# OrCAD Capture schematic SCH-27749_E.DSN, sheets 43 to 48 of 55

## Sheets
43 88E1543 1G Phy #2: size C
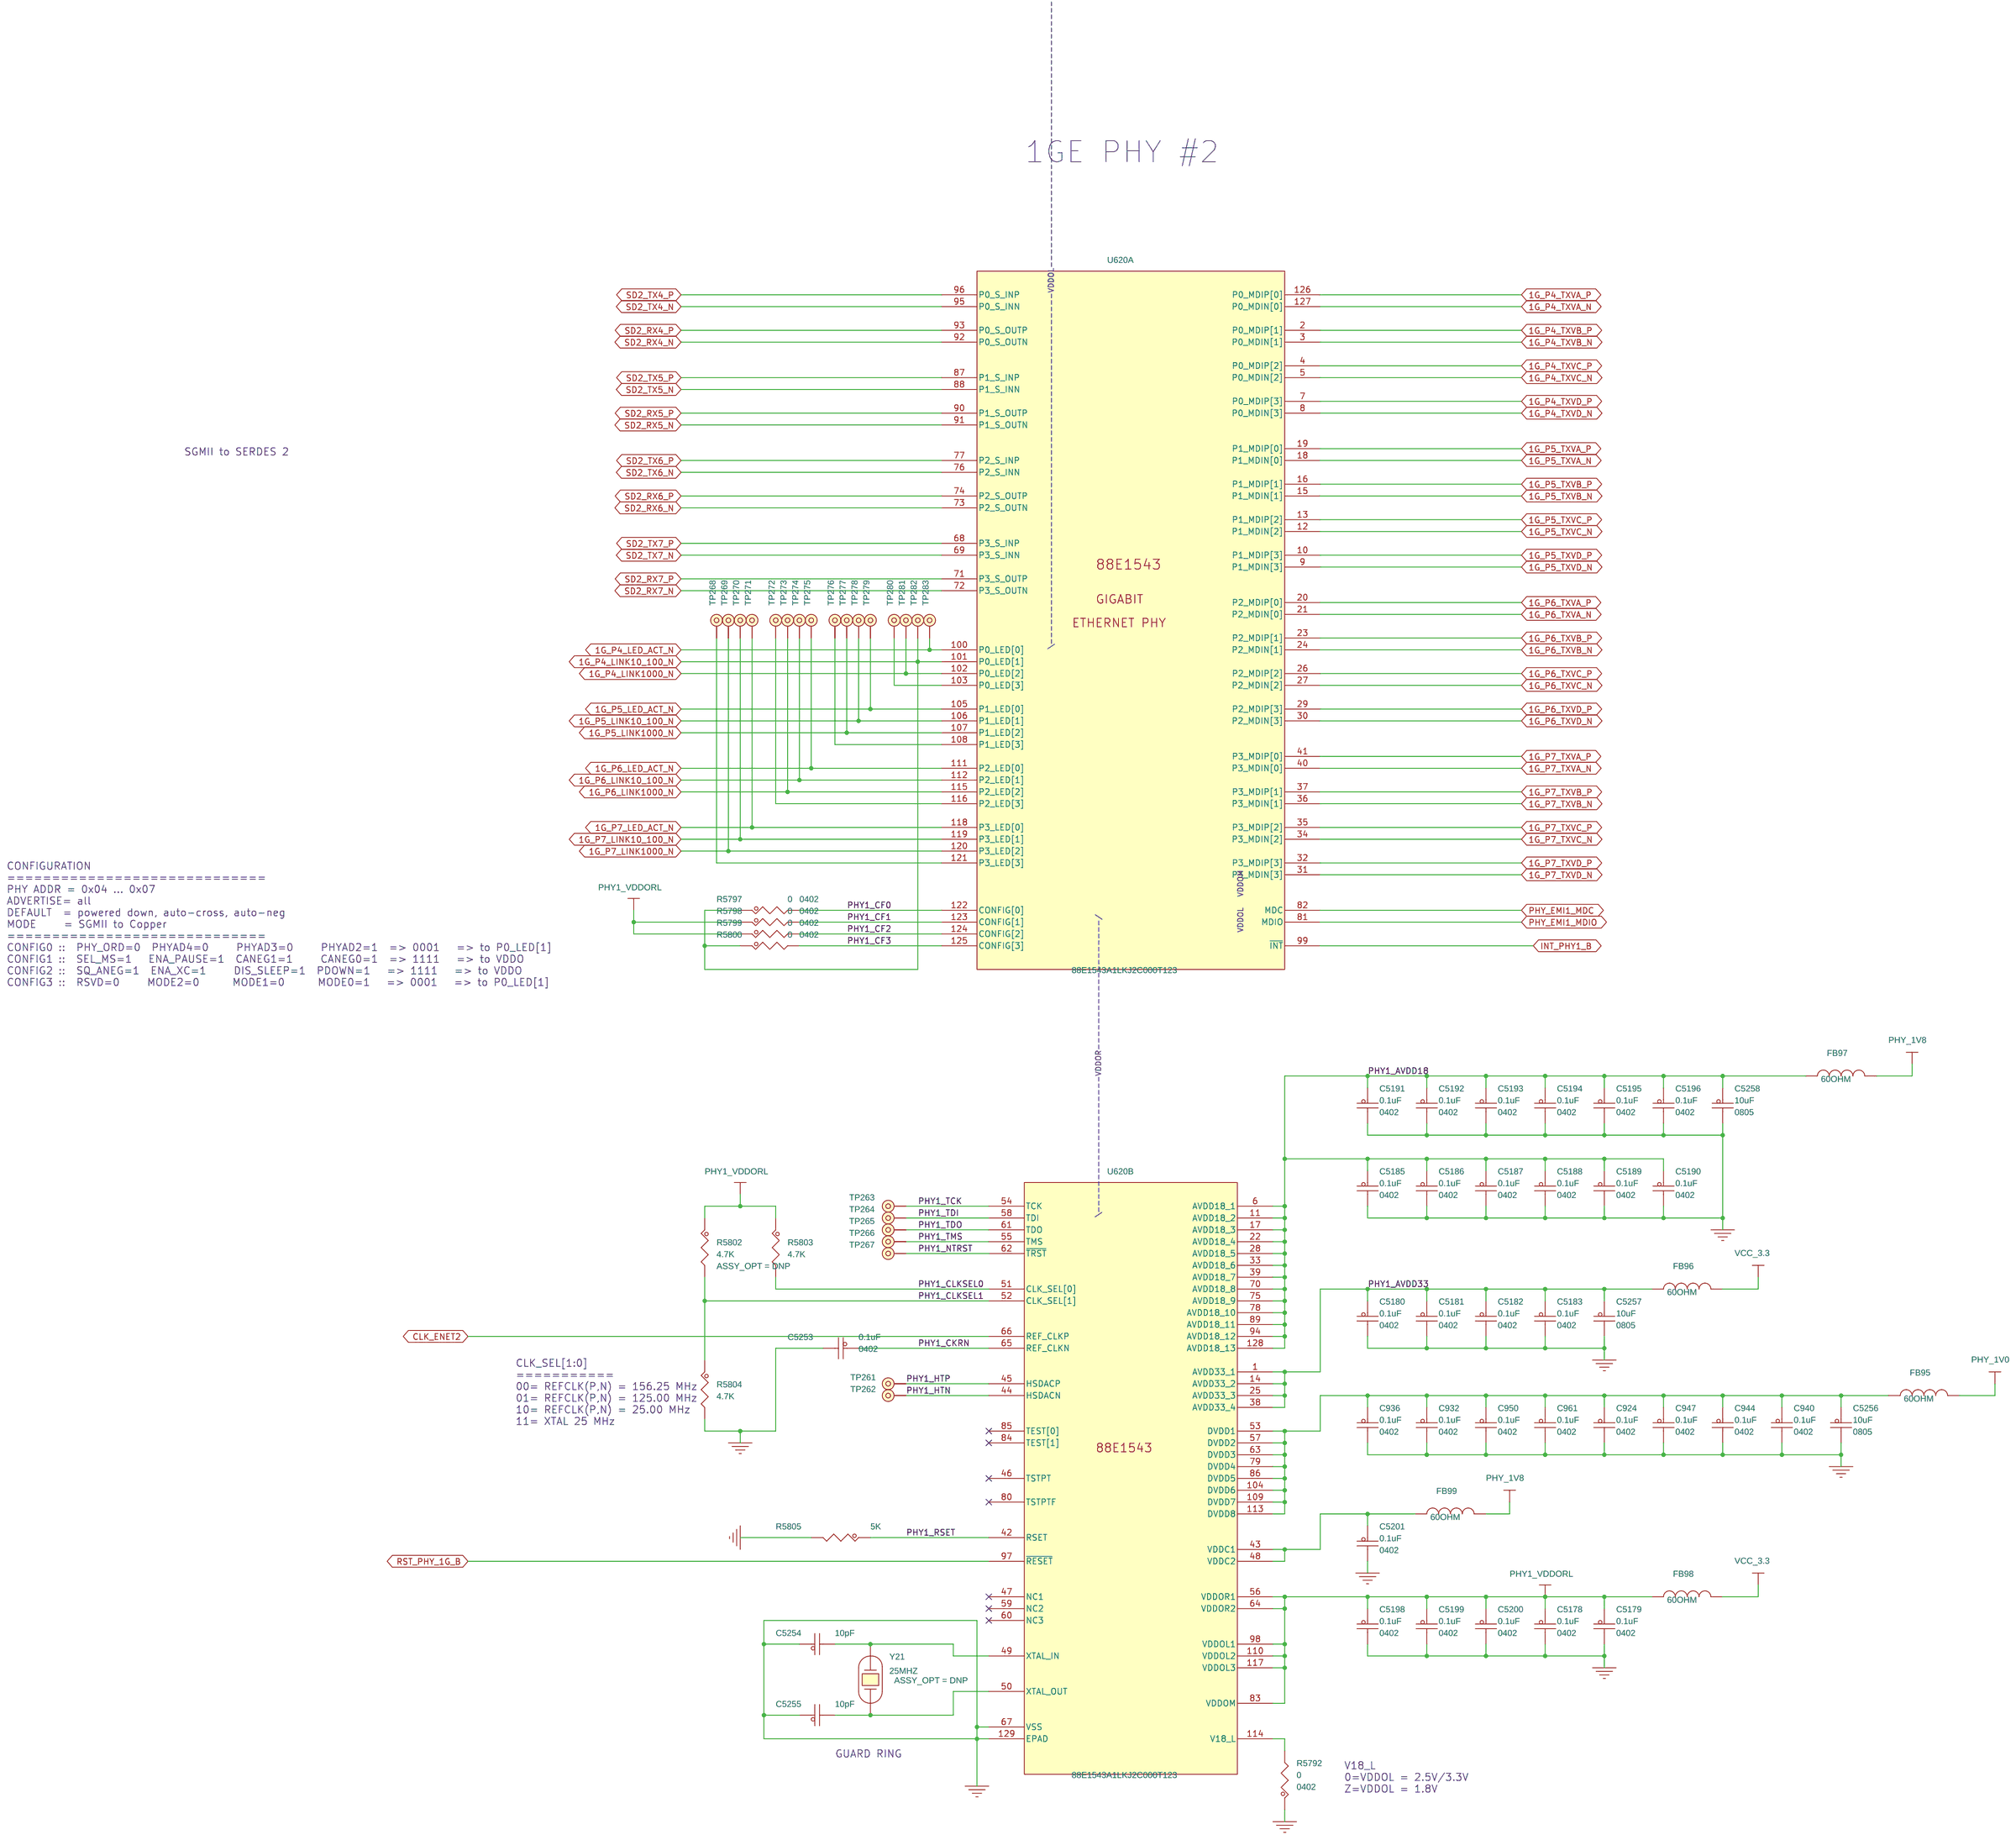
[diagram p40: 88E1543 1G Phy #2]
44 LAN1-8 RJ45 Conns: size C
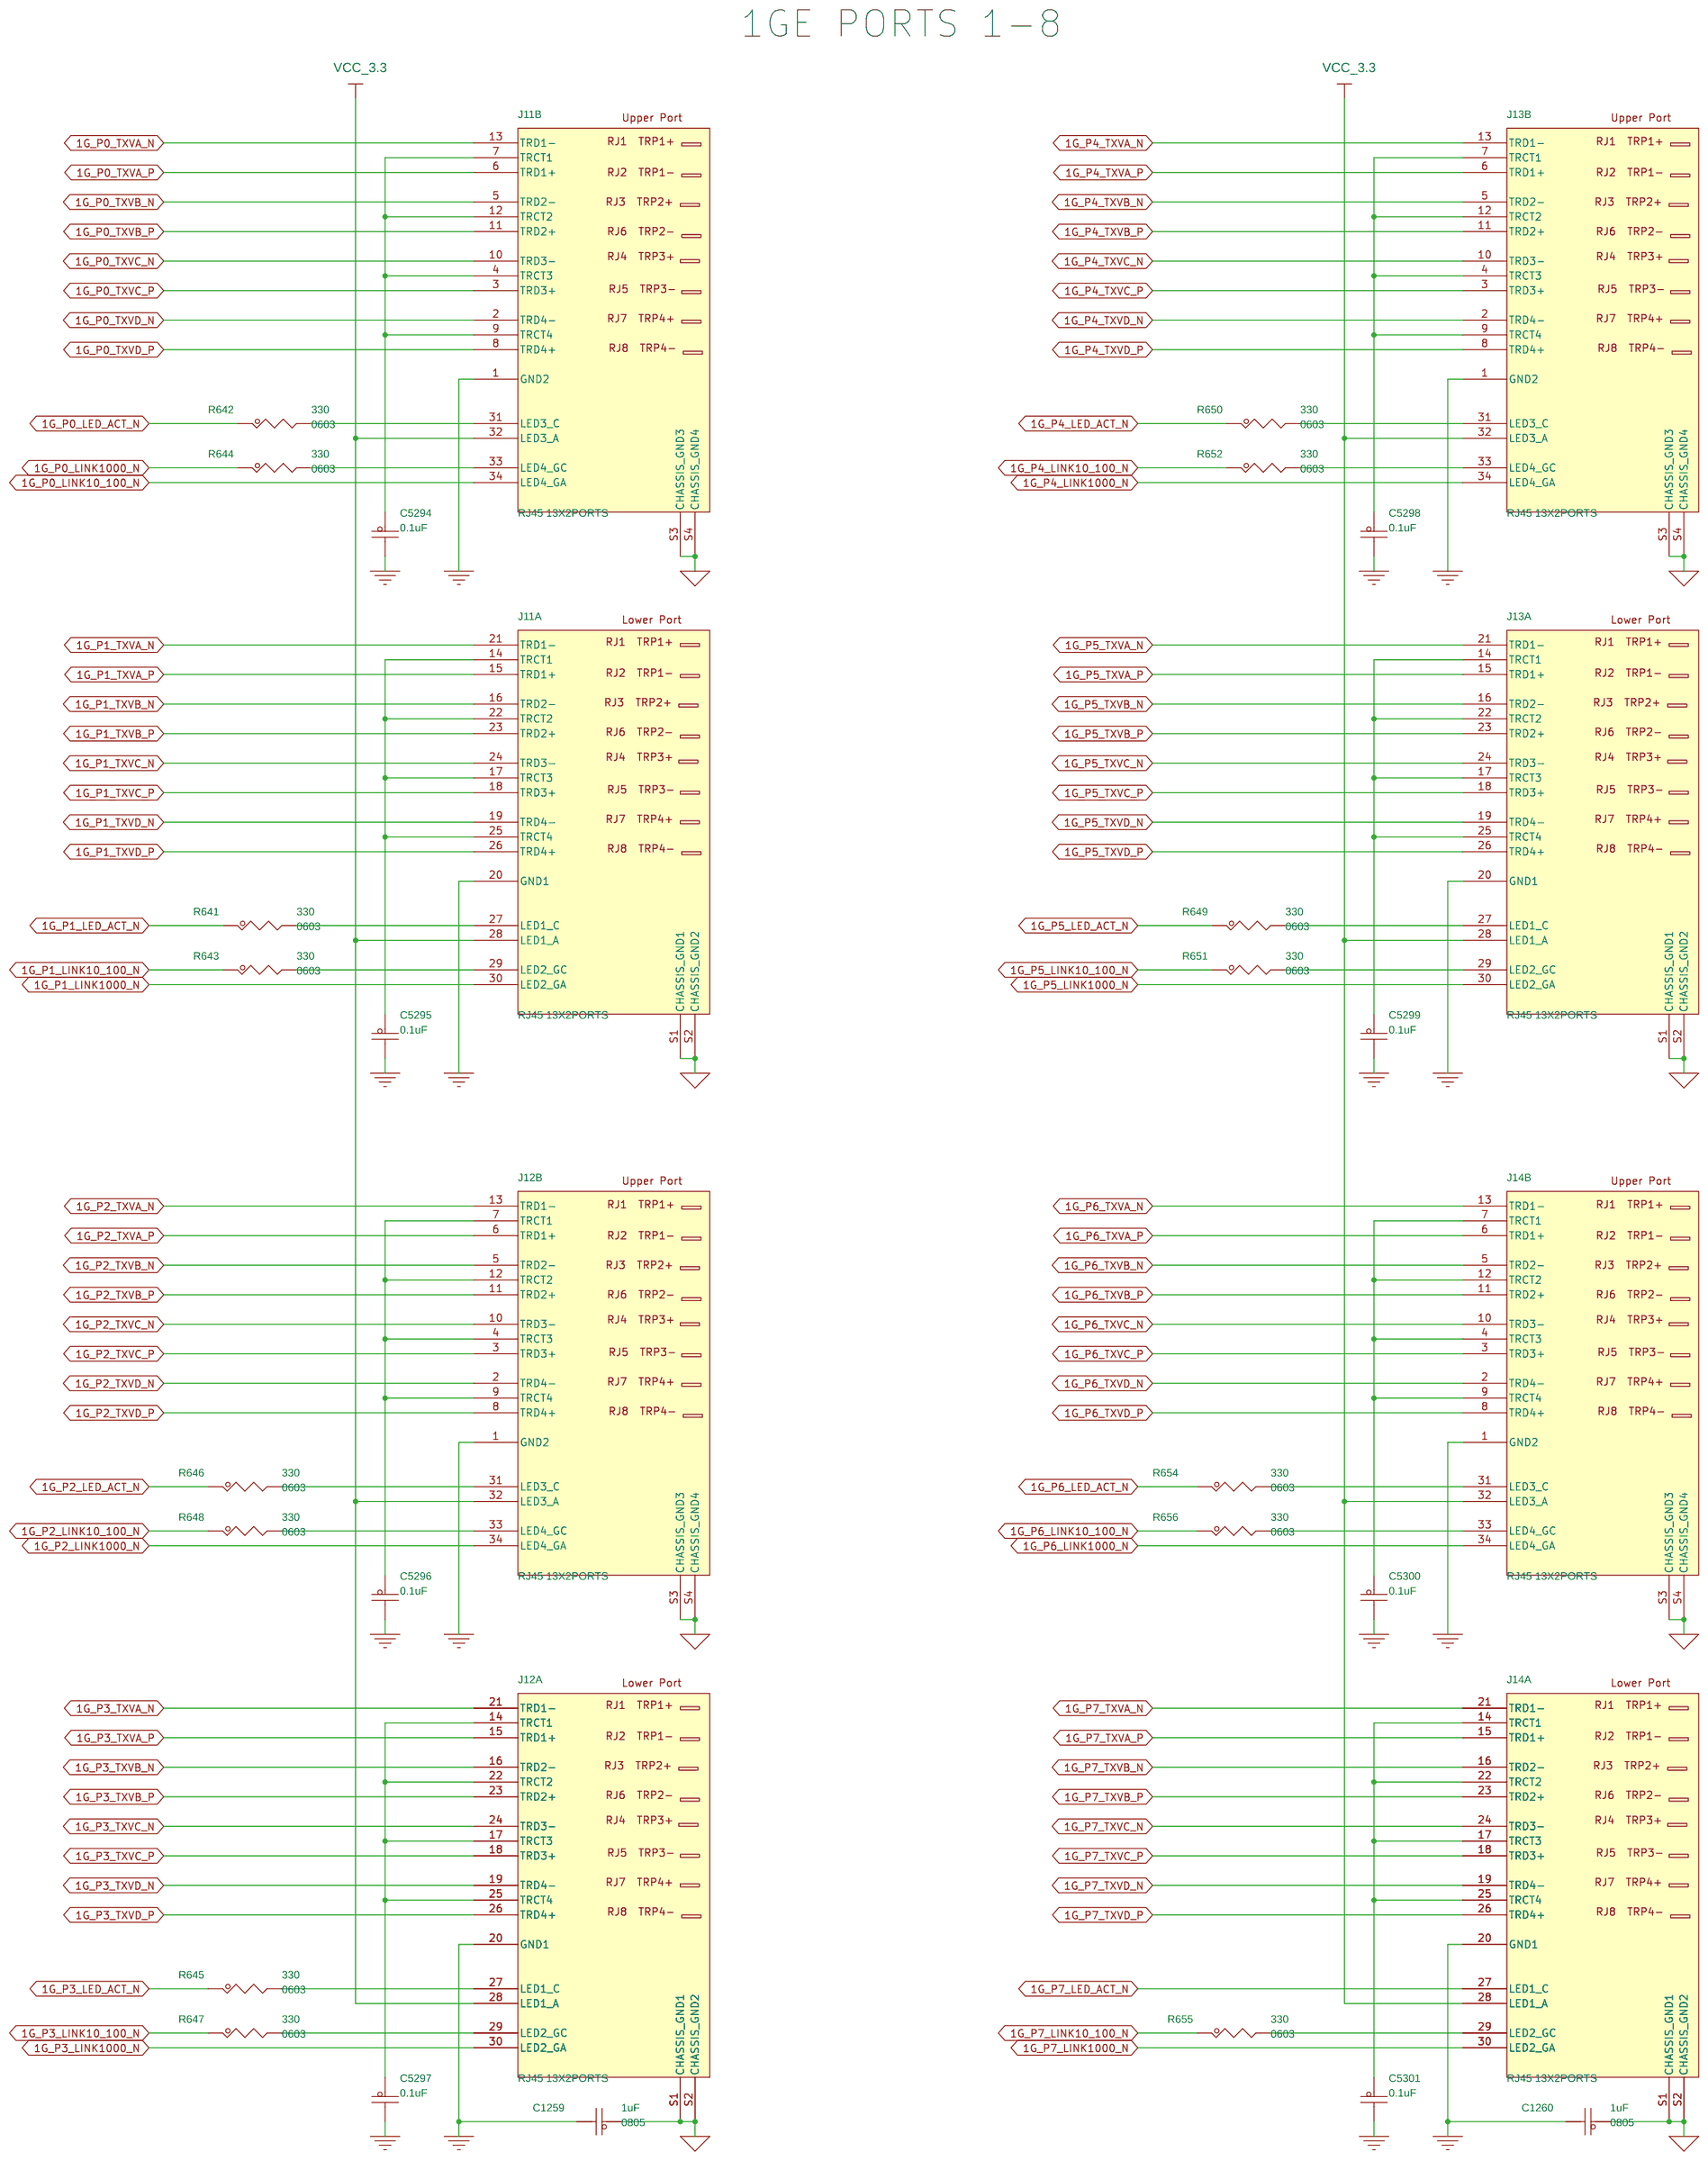
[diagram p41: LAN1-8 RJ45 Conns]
45 T4240 EMI + RGMII: size C
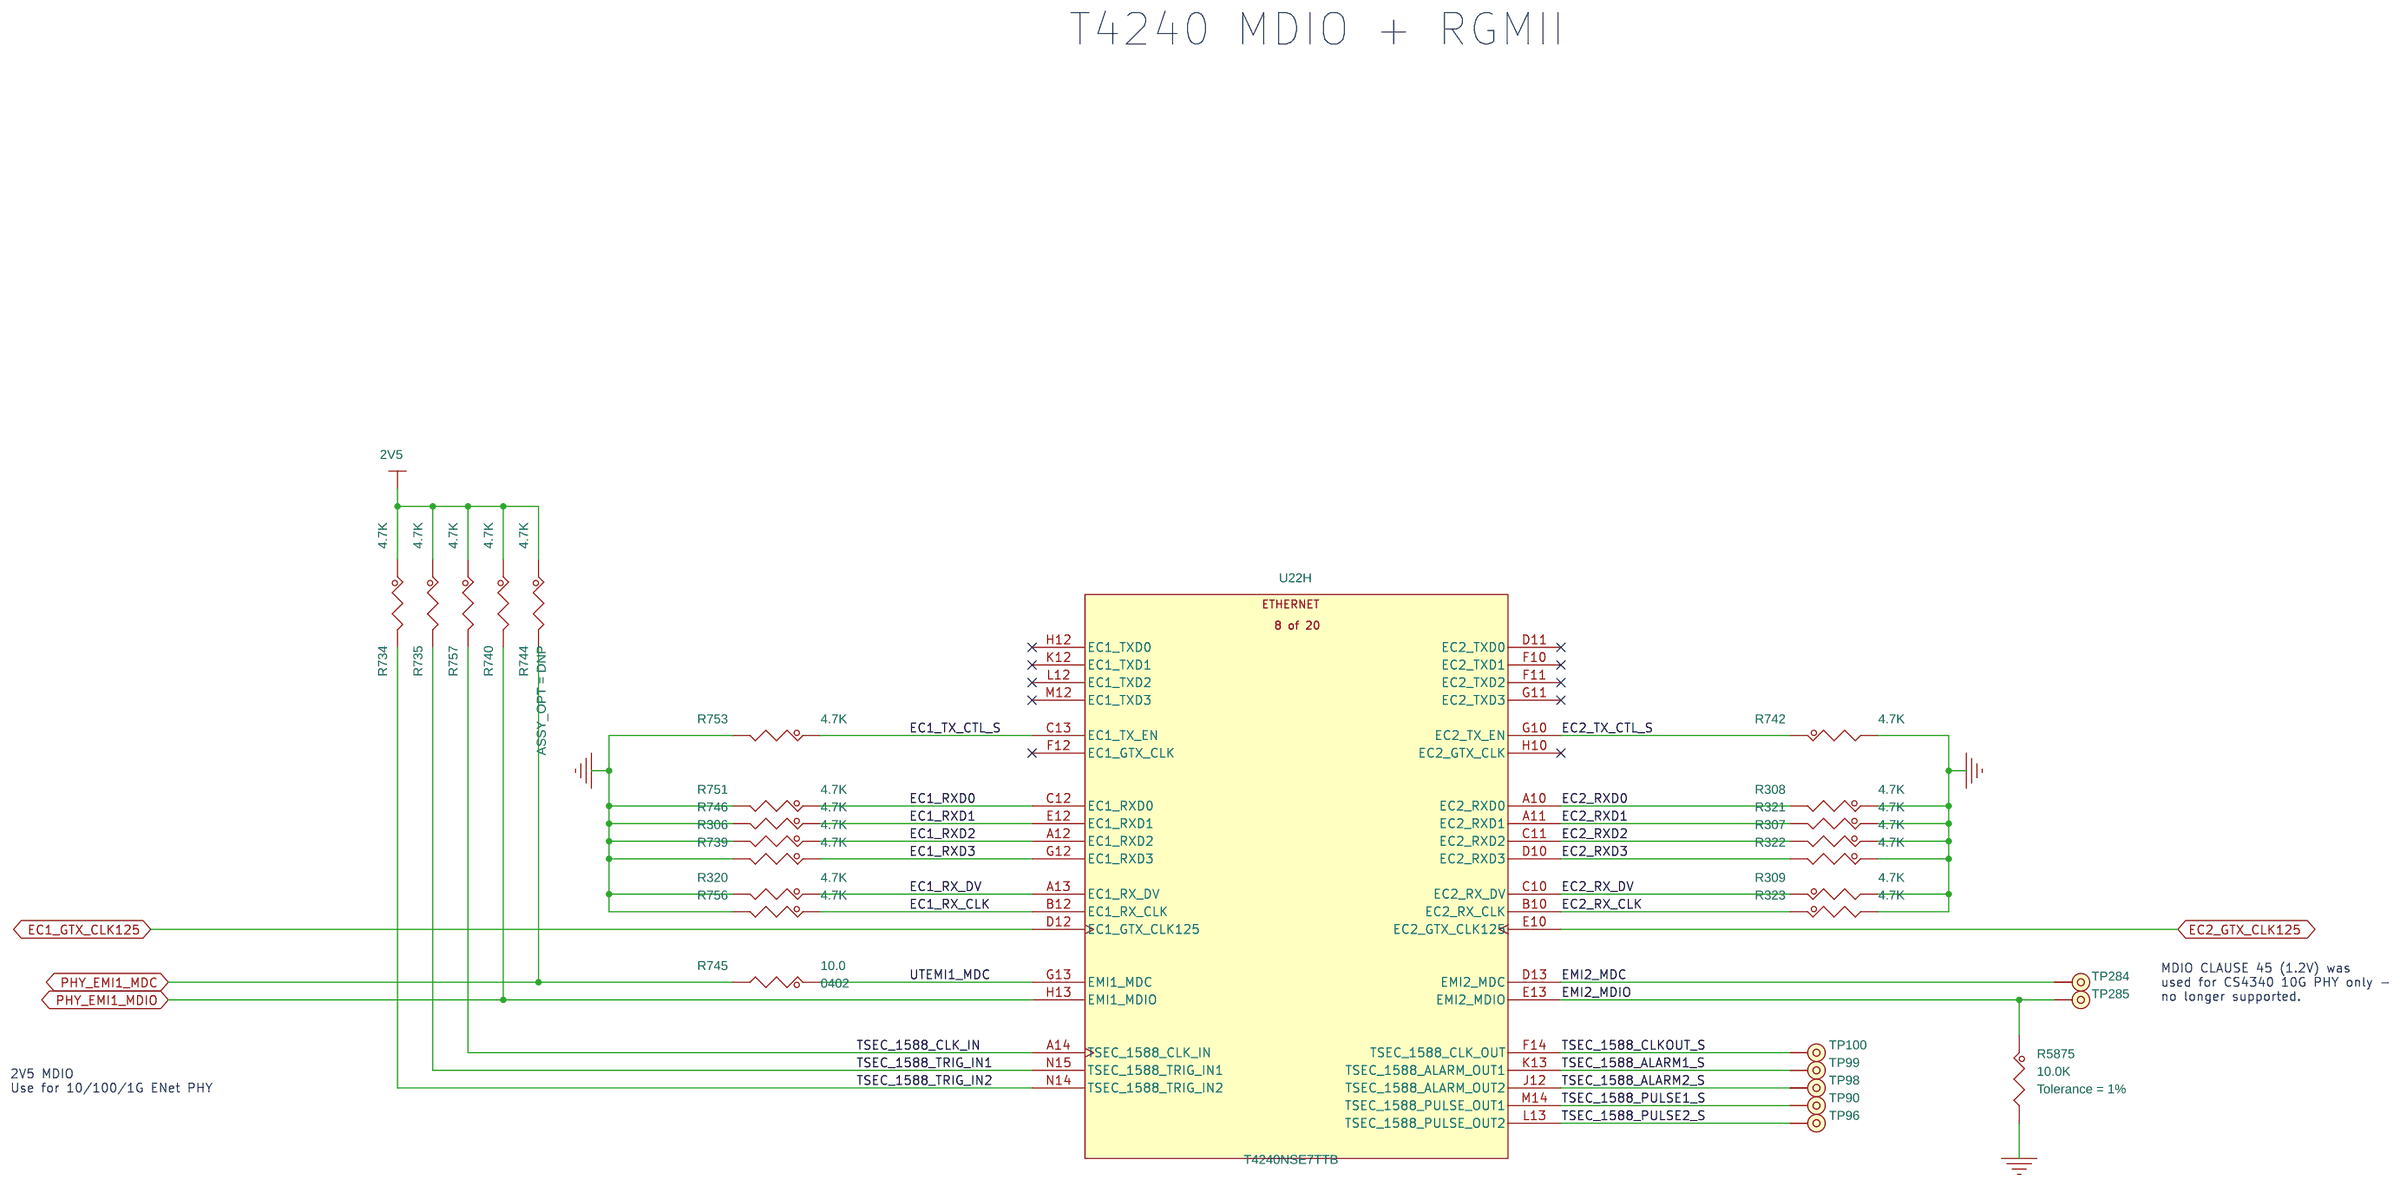
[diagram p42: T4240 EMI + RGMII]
46 T4240 SerDes 3 & 4: size C
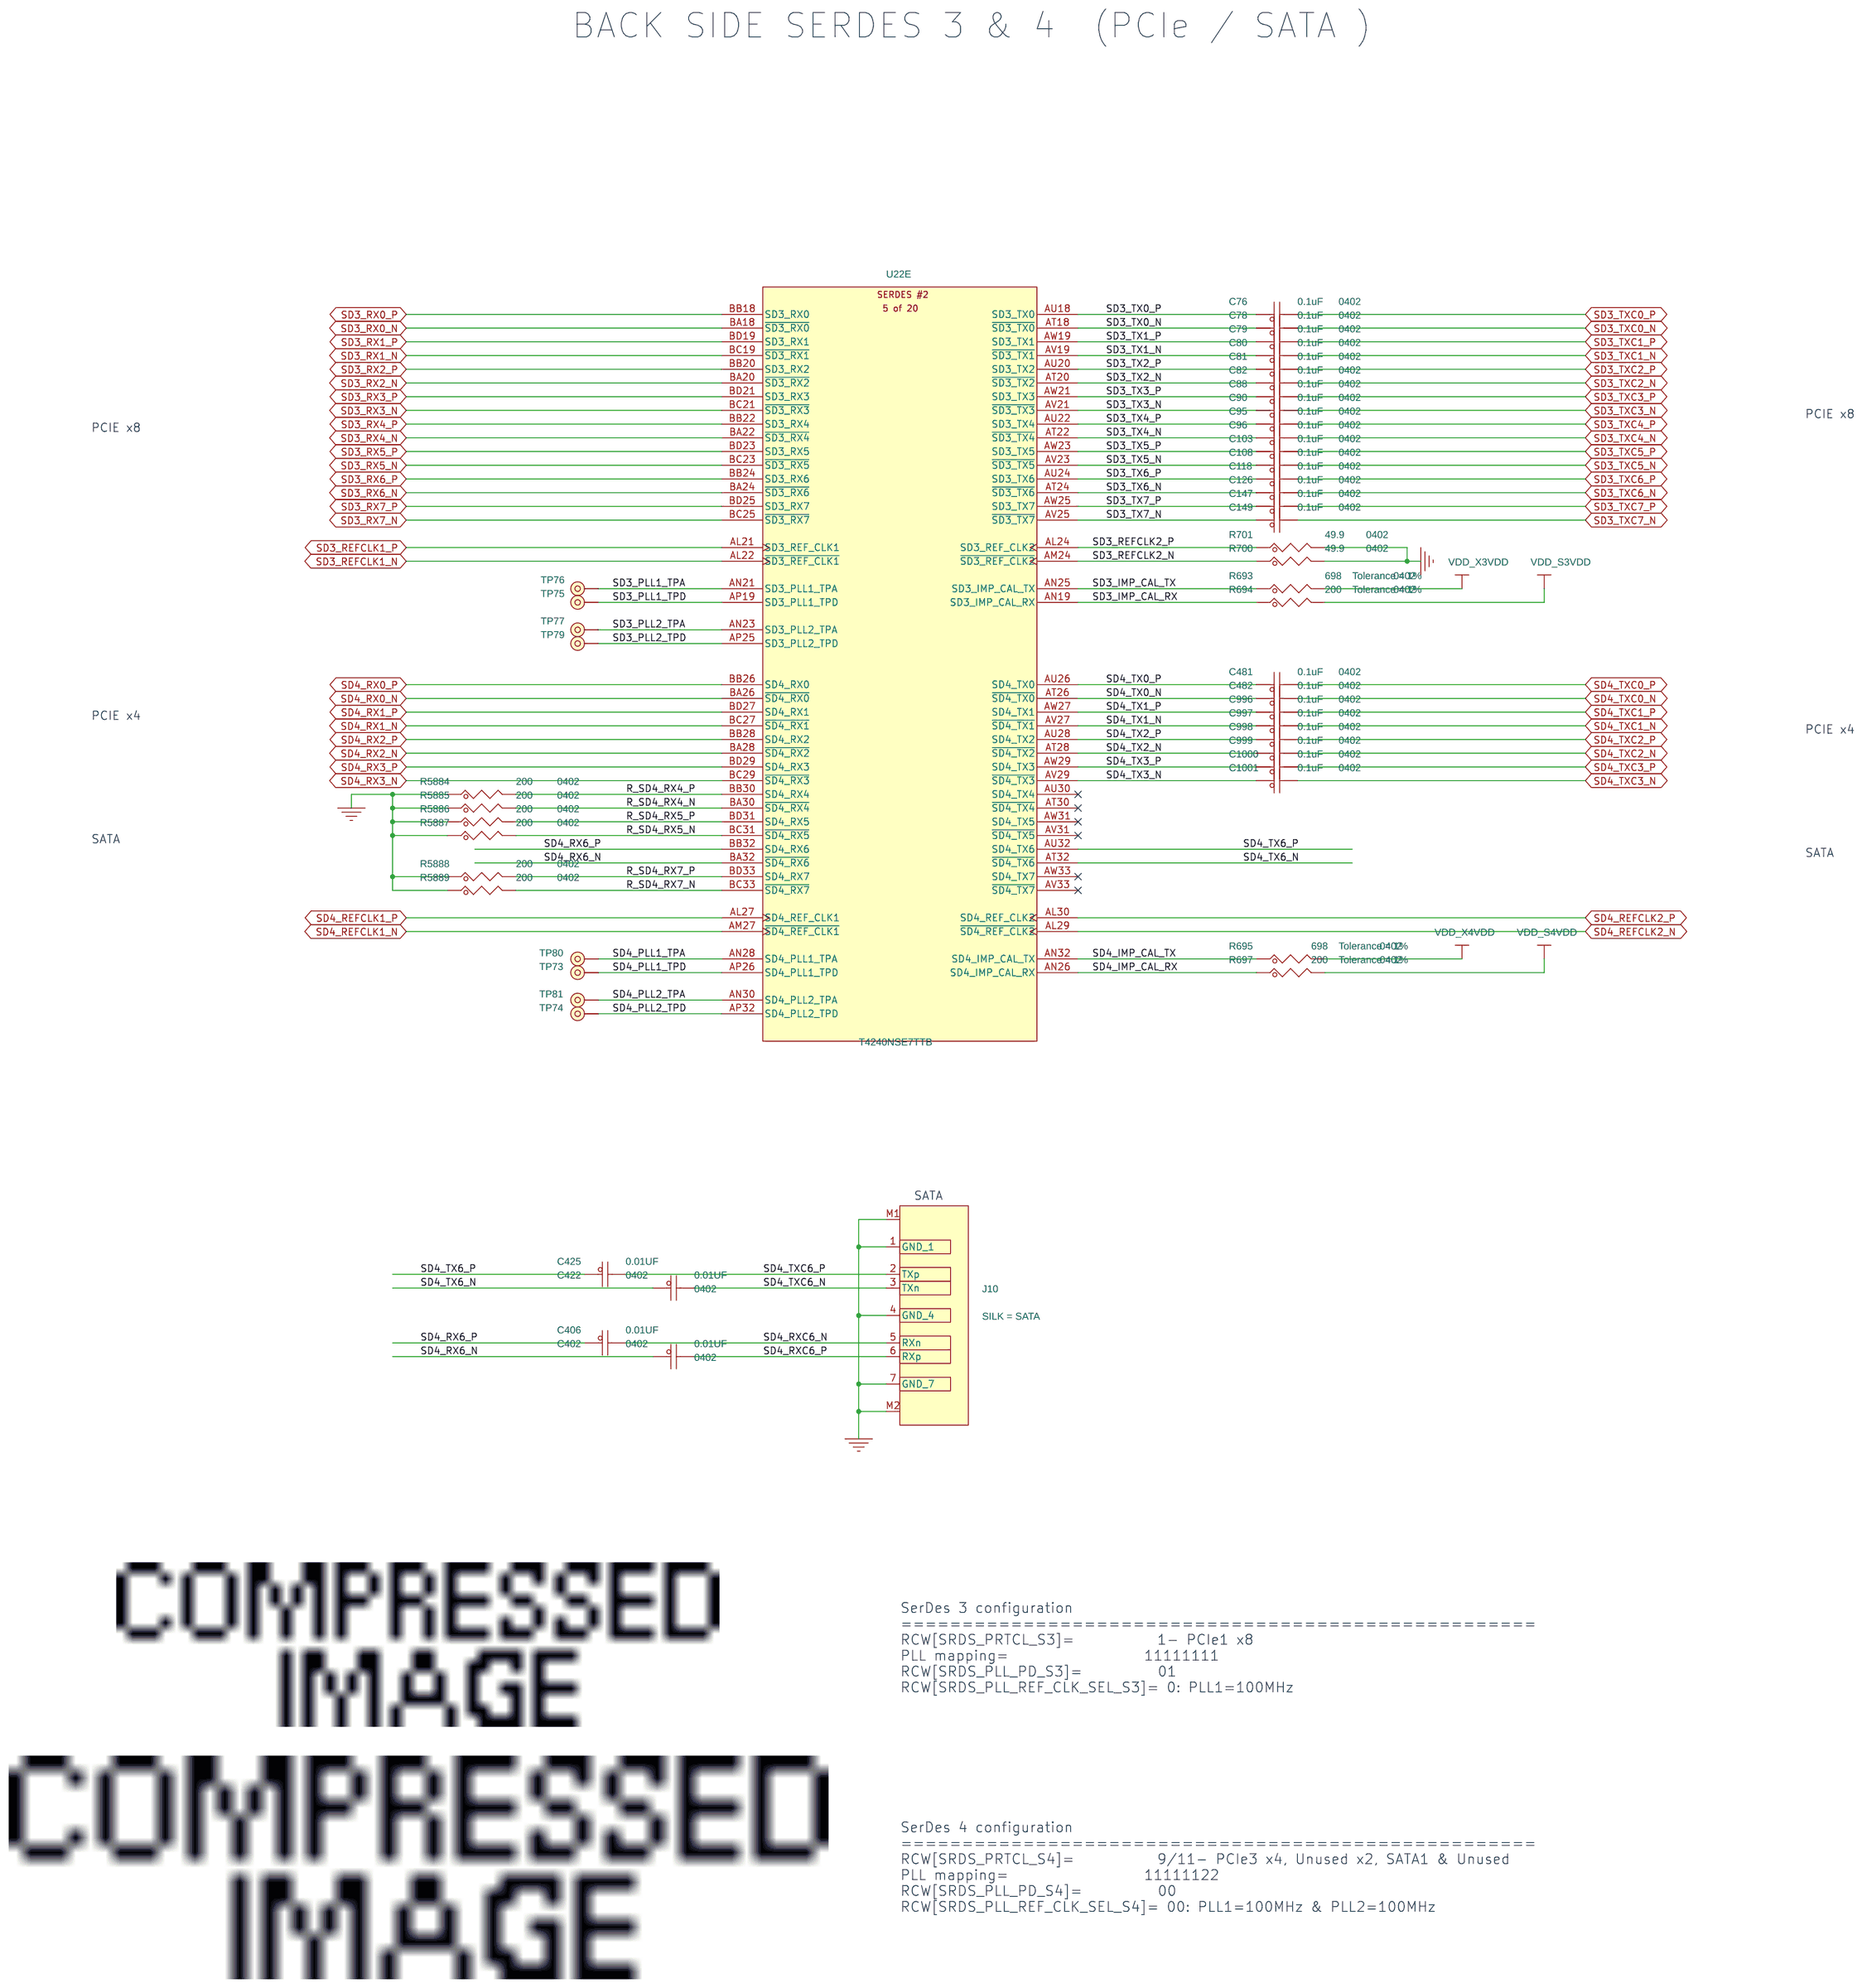
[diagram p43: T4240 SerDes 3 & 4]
47 PCIe Slot #1 x4: size C
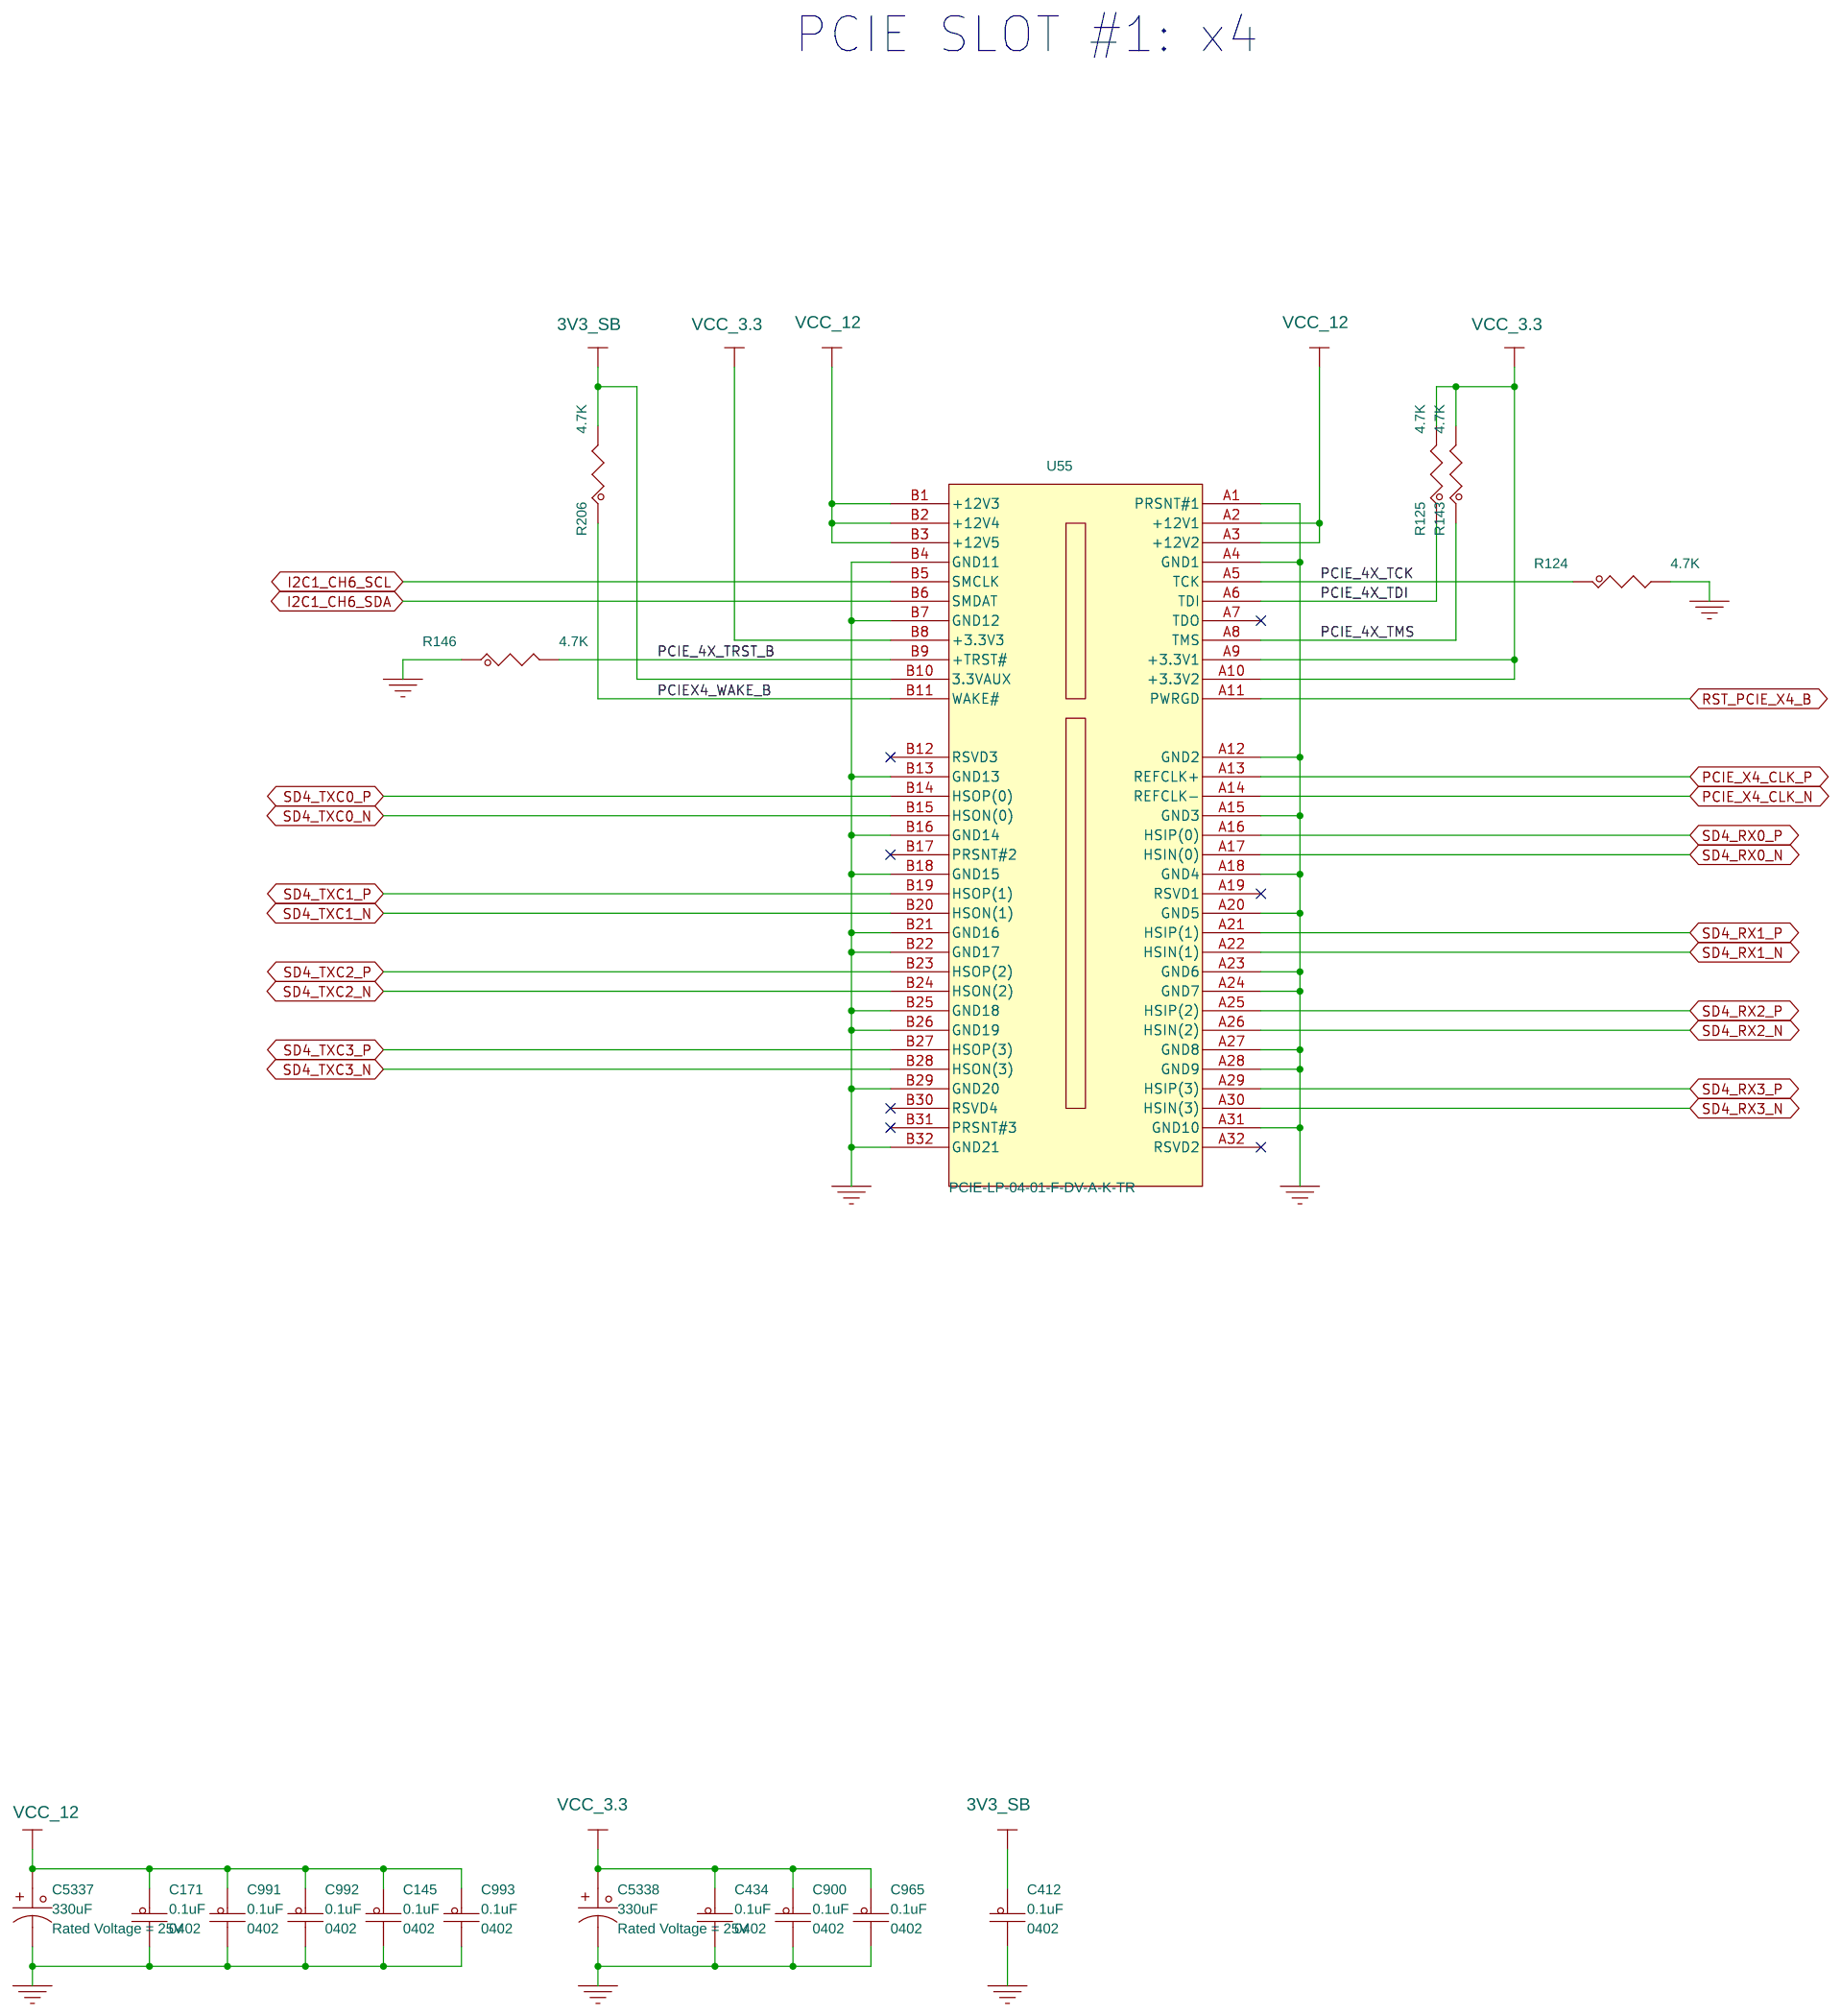
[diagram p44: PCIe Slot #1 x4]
48 PCIe Slot #2 x8: size C
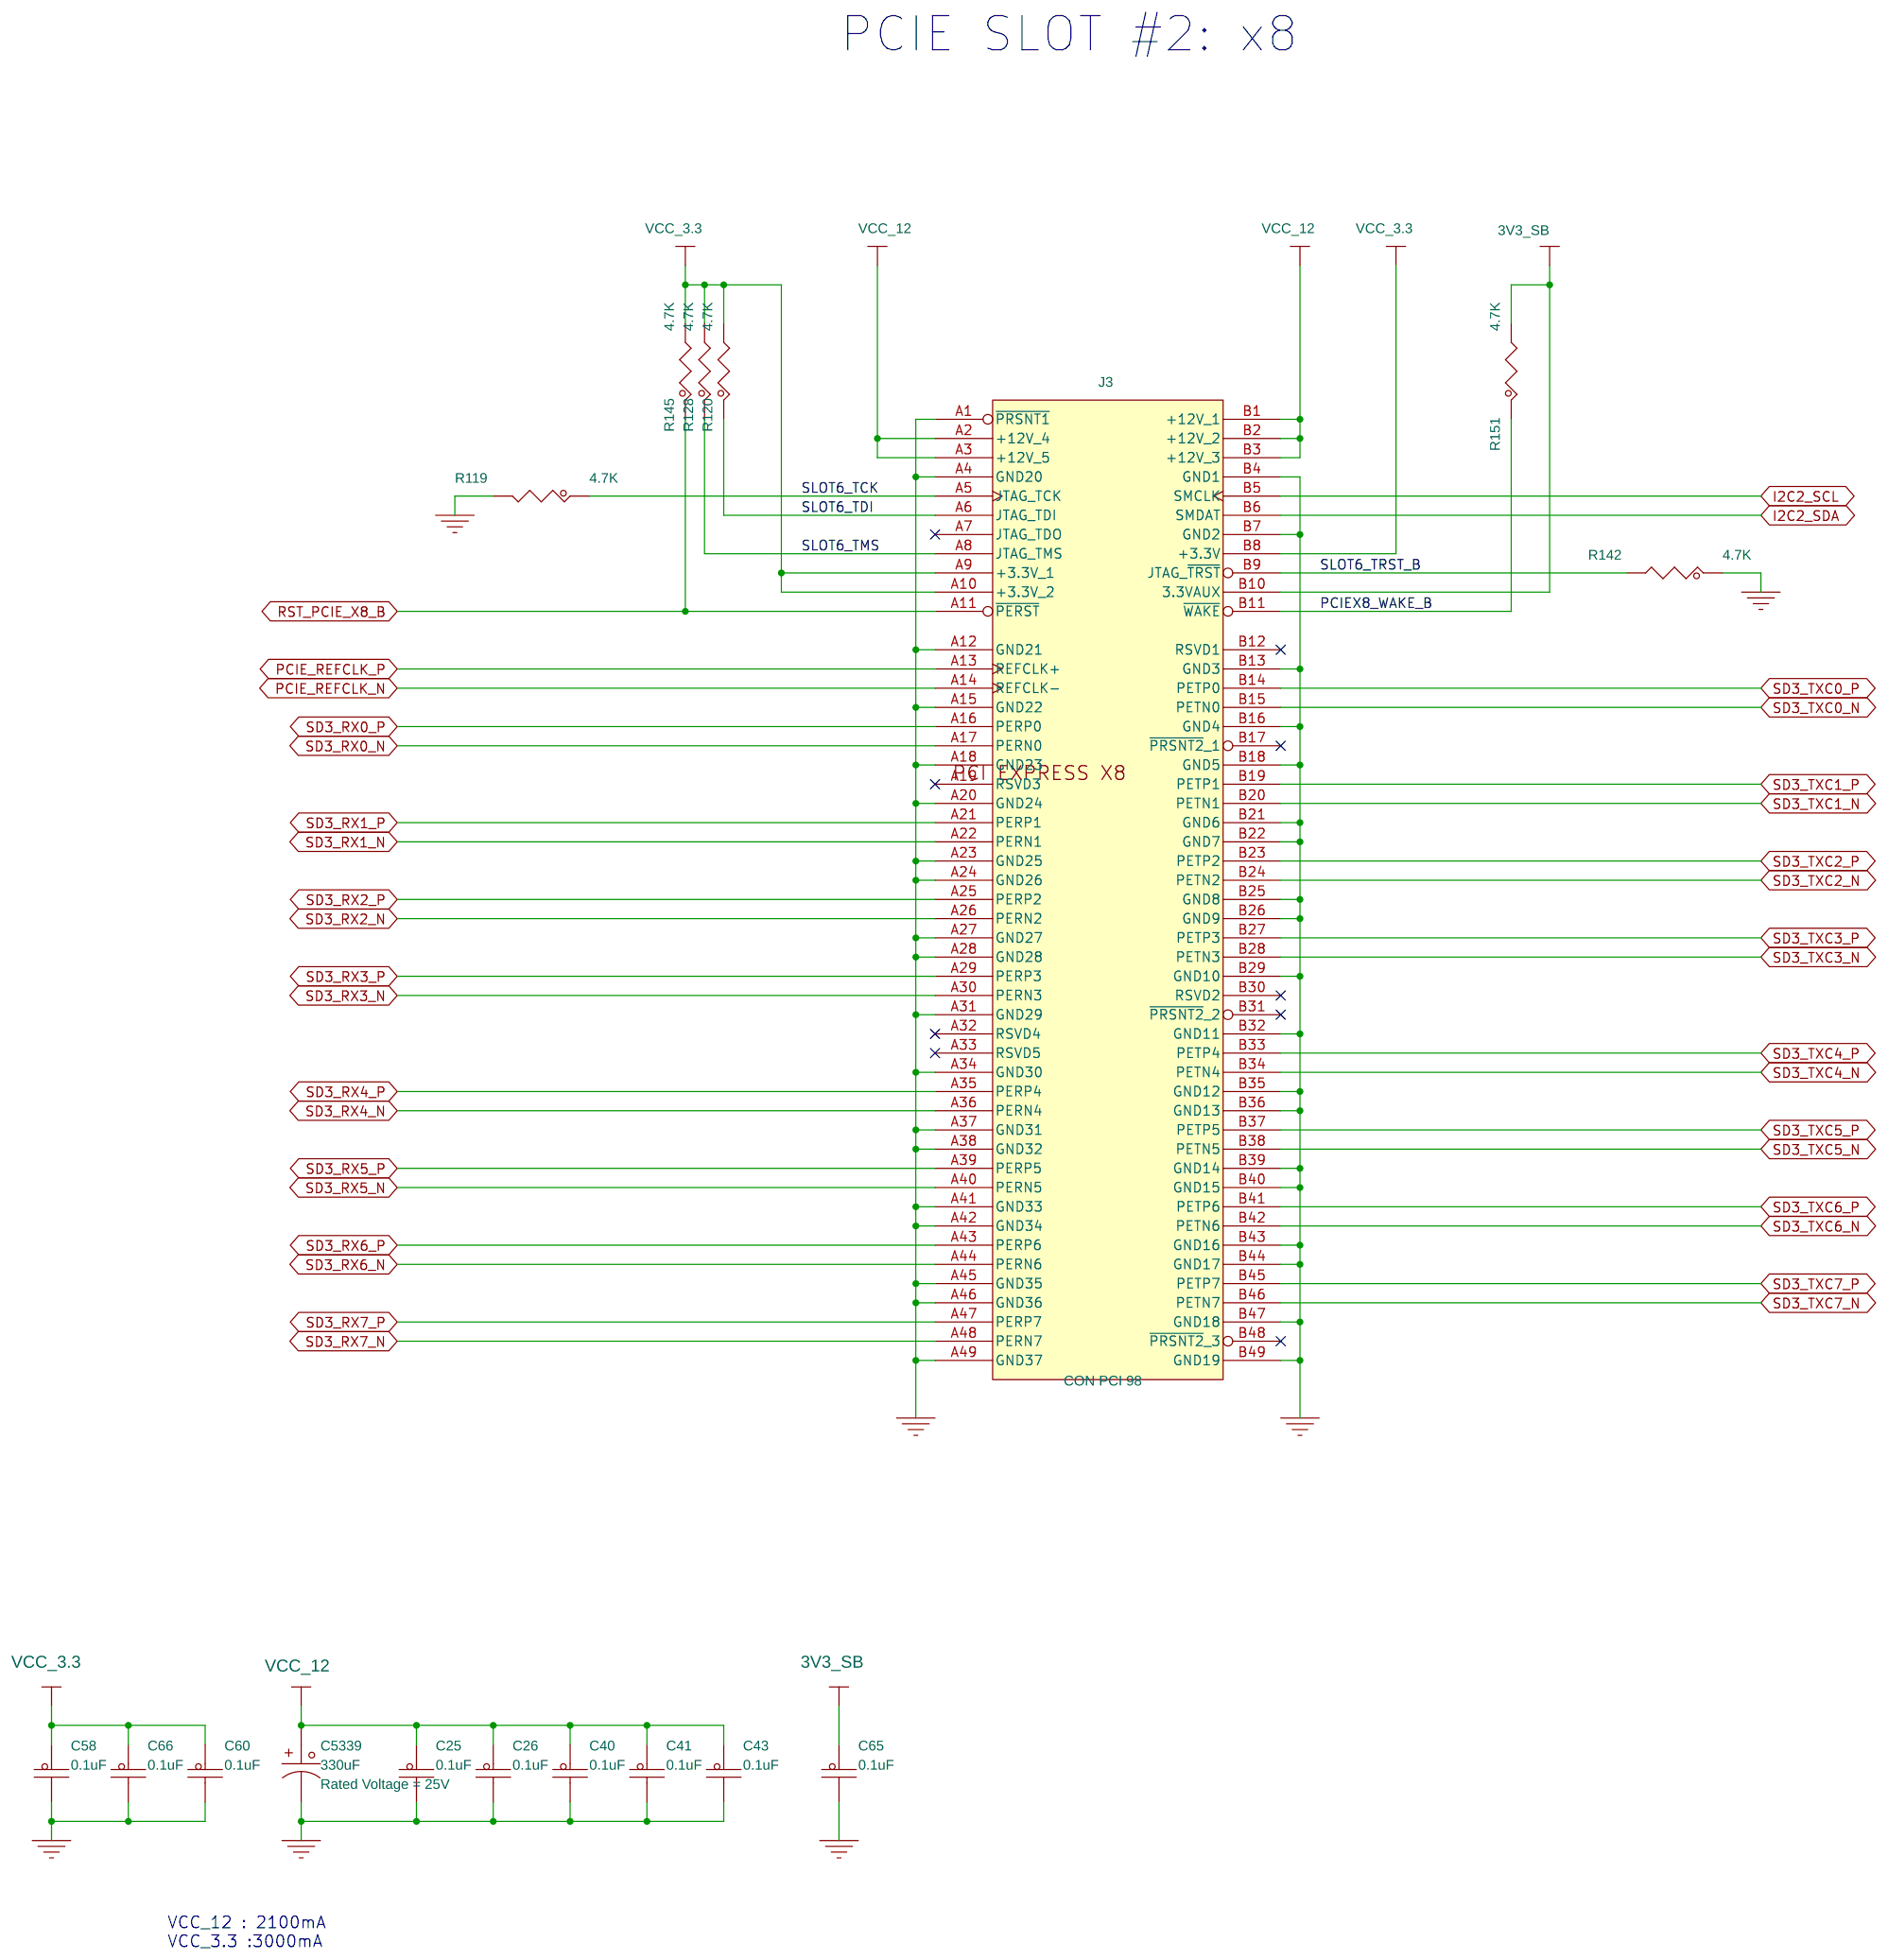
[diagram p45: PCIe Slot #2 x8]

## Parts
sheet 88E1543 1G Phy #2
C924  0.1uF  [CC0402_HD]
C932  0.1uF  [CC0402_HD]
C936  0.1uF  [CC0402_HD]
C940  0.1uF  [CC0402_HD]
C944  0.1uF  [CC0402_HD]
C947  0.1uF  [CC0402_HD]
C950  0.1uF  [CC0402_HD]
C961  0.1uF  [CC0402_HD]
C5178  0.1uF  [CC0402_HD]
C5179  0.1uF  [CC0402_HD]
C5180  0.1uF  [CC0402_HD]
C5181  0.1uF  [CC0402_HD]
C5182  0.1uF  [CC0402_HD]
C5183  0.1uF  [CC0402_HD]
C5185  0.1uF  [CC0402_HD]
C5186  0.1uF  [CC0402_HD]
C5187  0.1uF  [CC0402_HD]
C5188  0.1uF  [CC0402_HD]
C5189  0.1uF  [CC0402_HD]
C5190  0.1uF  [CC0402_HD]
C5191  0.1uF  [CC0402_HD]
C5192  0.1uF  [CC0402_HD]
C5193  0.1uF  [CC0402_HD]
C5194  0.1uF  [CC0402_HD]
C5195  0.1uF  [CC0402_HD]
C5196  0.1uF  [CC0402_HD]
C5198  0.1uF  [CC0402_HD]
C5199  0.1uF  [CC0402_HD]
C5200  0.1uF  [CC0402_HD]
C5201  0.1uF  [CC0402_HD]
C5253  0.1uF  [CC0402_HD]
C5254  10pF  [cc0402_hd]
C5255  10pF  [cc0402_hd]
C5256  10uF  [CC0603_OV]
C5257  10uF  [CC0603_OV]
C5258  10uF  [CC0603_OV]
FB95  60OHM  [ind_1p8x1mm_sm]
FB96  60OHM  [ind_1p8x1mm_sm]
FB97  60OHM  [ind_1p8x1mm_sm]
FB98  60OHM  [ind_1p8x1mm_sm]
FB99  60OHM  [ind_1p8x1mm_sm]
R5792  0  [RC0402_25]
R5797  0  [RC0402_25]
R5798  0  [RC0402_25]
R5799  0  [RC0402_25]
R5800  0  [RC0402_25]
R5802  4.7K  [RC0402_25]
R5803  4.7K  [RC0402_25]
R5804  4.7K  [RC0402_25]
R5805  5K  [RC0402_25]
TP261  TPAD_020  [tpad_020_top]
TP262  TPAD_020  [tpad_020_top]
TP263  TPAD_020  [tpad_020_top]
TP264  TPAD_020  [tpad_020_top]
TP265  TPAD_020  [tpad_020_top]
TP266  TPAD_020  [tpad_020_top]
TP267  TPAD_020  [tpad_020_top]
TP268  TPAD_020  [tpad_020_top]
TP269  TPAD_020  [tpad_020_top]
TP270  TPAD_020  [tpad_020_top]
TP271  TPAD_020  [tpad_020_top]
TP272  TPAD_020  [tpad_020_top]
TP273  TPAD_020  [tpad_020_top]
TP274  TPAD_020  [tpad_020_top]
TP275  TPAD_020  [tpad_020_top]
TP276  TPAD_020  [tpad_020_top]
TP277  TPAD_020  [tpad_020_top]
TP278  TPAD_020  [tpad_020_top]
TP279  TPAD_020  [tpad_020_top]
TP280  TPAD_020  [tpad_020_top]
TP281  TPAD_020  [tpad_020_top]
TP282  TPAD_020  [tpad_020_top]
TP283  TPAD_020  [tpad_020_top]
U620  88E1543A1LKJ2C000T123  [lqfp128_0p5_20x14_epad]  (sections A,B)
Y21  25MHZ  [xtal2_3p3x2p6]
sheet LAN1-8 RJ45 Conns
C1259  1uF  [CC0603_OV]
C1260  1uF  [CC0603_OV]
C5294  0.1uF  [CC0402_HD]
C5295  0.1uF  [CC0402_HD]
C5296  0.1uF  [CC0402_HD]
C5297  0.1uF  [CC0402_HD]
C5298  0.1uF  [CC0402_HD]
C5299  0.1uF  [CC0402_HD]
C5300  0.1uF  [CC0402_HD]
C5301  0.1uF  [CC0402_HD]
J11  RJ45 13X2PORTS  [CON_RJ45_2X1_MAG_LED]  (sections A,B)
J12  RJ45 13X2PORTS  [CON_RJ45_2X1_MAG_LED]  (sections A,B)
J13  RJ45 13X2PORTS  [CON_RJ45_2X1_MAG_LED]  (sections A,B)
J14  RJ45 13X2PORTS  [CON_RJ45_2X1_MAG_LED]  (sections A,B)
R641  330  [RC0402_25]
R642  330  [RC0402_25]
R643  330  [RC0402_25]
R644  330  [RC0402_25]
R645  330  [RC0402_25]
R646  330  [RC0402_25]
R647  330  [RC0402_25]
R648  330  [RC0402_25]
R649  330  [RC0402_25]
R650  330  [RC0402_25]
R651  330  [RC0402_25]
R652  330  [RC0402_25]
R654  330  [RC0402_25]
R655  330  [RC0402_25]
R656  330  [RC0402_25]
sheet PCIe Slot #1 x4
C145  0.1uF  [CC0402_HD]
C171  0.1uF  [CC0402_HD]
C412  0.1uF  [CC0402_HD]
C434  0.1uF  [CC0402_HD]
C900  0.1uF  [CC0402_HD]
C965  0.1uF  [CC0402_HD]
C991  0.1uF  [CC0402_HD]
C992  0.1uF  [CC0402_HD]
C993  0.1uF  [CC0402_HD]
C5337  330uF  [cap_10p5_rad]
C5338  330uF  [cap_10p5_rad]
R124  4.7K  [RC0402_25]
R125  4.7K  [RC0402_25]
R143  4.7K  [RC0402_25]
R146  4.7K  [RC0402_25]
R206  4.7K  [RC0402_25]
U55  PCIE-LP-04-01-F-DV-A-K-TR  [con64_1mm_sm_pcie_lp]
sheet PCIe Slot #2 x8
C25  0.1uF  [CC0402_HD]
C26  0.1uF  [CC0402_HD]
C40  0.1uF  [CC0402_HD]
C41  0.1uF  [CC0402_HD]
C43  0.1uF  [CC0402_HD]
C58  0.1uF  [CC0402_HD]
C60  0.1uF  [CC0402_HD]
C65  0.1uF  [CC0402_HD]
C66  0.1uF  [CC0402_HD]
C5339  330uF  [cap_10p5_rad]
J3  CON PCI 98  [con_pcie_98_1mm_th_122l]
R119  4.7K  [RC0402_25]
R120  4.7K  [RC0402_25]
R128  4.7K  [RC0402_25]
R142  4.7K  [RC0402_25]
R145  4.7K  [RC0402_25]
R151  4.7K  [RC0402_25]
sheet T4240 DDR Controller #2
U22  T4240NSE7TTB  [BGA1932_1MM_45X45MM]  (sections A,B,C,D,E,F,G,H,I,J,K,L,M,N,O,P,Q,R,S,T)
sheet T4240 EMI + RGMII
R306  4.7K  [RC0402_25]
R307  4.7K  [RC0402_25]
R308  4.7K  [RC0402_25]
R309  4.7K  [RC0402_25]
R320  4.7K  [RC0402_25]
R321  4.7K  [RC0402_25]
R322  4.7K  [RC0402_25]
R323  4.7K  [RC0402_25]
R734  4.7K  [RC0402_25]
R735  4.7K  [RC0402_25]
R739  4.7K  [RC0402_25]
R740  4.7K  [RC0402_25]
R742  4.7K  [RC0402_25]
R744  4.7K  [RC0402_25]
R745  10.0  [RC0402_25]
R746  4.7K  [RC0402_25]
R751  4.7K  [RC0402_25]
R753  4.7K  [RC0402_25]
R756  4.7K  [RC0402_25]
R757  4.7K  [RC0402_25]
R5875  10.0K  [RC0402_25]
TP90  TPAD_020  [tpad_020_top]
TP96  TPAD_020  [tpad_020_top]
TP98  TPAD_020  [tpad_020_top]
TP99  TPAD_020  [tpad_020_top]
TP100  TPAD_020  [tpad_020_top]
TP284  TPAD_020  [tpad_020_top]
TP285  TPAD_020  [tpad_020_top]
sheet T4240 SerDes 3 & 4
C76  0.1uF  [CC0402_HD]
C78  0.1uF  [CC0402_HD]
C79  0.1uF  [CC0402_HD]
C80  0.1uF  [CC0402_HD]
C81  0.1uF  [CC0402_HD]
C82  0.1uF  [CC0402_HD]
C88  0.1uF  [CC0402_HD]
C90  0.1uF  [CC0402_HD]
C95  0.1uF  [CC0402_HD]
C96  0.1uF  [CC0402_HD]
C103  0.1uF  [CC0402_HD]
C108  0.1uF  [CC0402_HD]
C118  0.1uF  [CC0402_HD]
C126  0.1uF  [CC0402_HD]
C147  0.1uF  [CC0402_HD]
C149  0.1uF  [CC0402_HD]
C402  0.01UF  [CC0402_HD]
C406  0.01UF  [CC0402_HD]
C422  0.01UF  [CC0402_HD]
C425  0.01UF  [CC0402_HD]
C481  0.1uF  [CC0402_HD]
C482  0.1uF  [CC0402_HD]
C996  0.1uF  [CC0402_HD]
C997  0.1uF  [CC0402_HD]
C998  0.1uF  [CC0402_HD]
C999  0.1uF  [CC0402_HD]
C1000  0.1uF  [CC0402_HD]
C1001  0.1uF  [CC0402_HD]
J10  HDR 1X7  [CON_7_SATA_V_SM]
R693  698  [RC0402_25]
R694  200  [RC0402_25]
R695  698  [RC0402_25]
R697  200  [RC0402_25]
R700  49.9  [RC0402_25]
R701  49.9  [RC0402_25]
R5884  200  [RC0402_25]
R5885  200  [RC0402_25]
R5886  200  [RC0402_25]
R5887  200  [RC0402_25]
R5888  200  [RC0402_25]
R5889  200  [RC0402_25]
TP73  TPAD_020  [tpad_020_top]
TP74  TPAD_020  [tpad_020_top]
TP75  TPAD_020  [tpad_020_top]
TP76  TPAD_020  [tpad_020_top]
TP77  TPAD_020  [tpad_020_top]
TP79  TPAD_020  [tpad_020_top]
TP80  TPAD_020  [tpad_020_top]
TP81  TPAD_020  [tpad_020_top]

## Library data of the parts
C76 C78-C82 C88 C90 C95 C96 C103 C108 C118 C126 C145 C147 C149 C171 C412 C434 C481 C482 C900 C924 C932 C936 C940 C944 C947 C950 C961 C965 C991-C993 C996-C1001 C5178-C5183 C5185-C5196 C5198-C5201 C5253 = CAP_NP: CAP CER 0.1uF 16V 10% X7R AEC-Q200 0402; AGILE_PN: 150-79025; CAD_APPROVED: Yes; FPLIST: CC0402_25,CC0402_HD,0402_CC,capc0402_l; HEIGHT: 0.55MM; MFG_NAME01: MURATA; MFG_PN01: GCM155R71C104KA55D; Package: 0402; Package Size: 0402; Package Type: ø180mm Reel PAPER; Part Number: 4CC104B163X00; Product Name: (H)MLCC 0.1uF/16V +-10% 0402 X7R; ROHS: Yes; Rated Voltage: 16V; Temp Range: -55C to +125C; Tolerance: 10%
C5254 C5255 = CAP_NP: CAP CER 10pF 50V 1% C0G AEC-Q200 0402; 3D_Mechanical_Footprint_File: http://fcl.am.freescale.net/ALLEGRO/step/cc0402_25.STEP; AGILE_PN: 150-81416; CAD_APPROVED: Yes; FPLIST: cc0402_25,cc0402_hd,0402_cc,capc0402_l; HEIGHT: 0.55MM; MFG_NAME01: MURATA; MFG_PN01: GCM1555C1H100FA16; Package Size: 0402; Package Type: SMD/SMT; ROHS: Yes; Rated Voltage: 50V; Temp Range: -55C to +125C; Tolerance: 1%
C5256-C5258 = CAP_NP: CAP CER 10UF 10V 10% X5R 0603; AGILE_PN: 150-78675; CAD_APPROVED: Yes; FPLIST: CC0603_OV,CC0603,0603_CC_NSP; HEIGHT: 1.016MM; MFG_NAME01: MURATA; MFG_PN01: GRM188R61A106KE69D; Package: 0805; Part Number: 4CC106D101X00; Product Name: (H)MLCC 10uF/10V +/-10% 0805 X5R; ROHS: Yes; Rated Voltage: 10V; Temp Range: -55C to +85C; Tolerance: 10%
FB95-FB99 = INDUCTOR: IND FER BEAD 60OHM@100MHz 3A 25% 0603; 3D_Mechanical_Footprint_File: http://fcl.am.freescale.net/ALLEGRO/step/ind_1p8x1mm_sm.step; AGILE_PN: 180-78461; CAD_APPROVED: Yes; HEIGHT: 1MM; MFG_NAME01: WURTH ELEKTRONIK EISOS GMBH & CO. KG (ELECTRONIC & ELECTROMEHANICAL COMP); MFG_PN01: 742792602; ROHS: Yes
R5792 R5797-R5800 = RES: RES MF ZERO OHM 1/10W -- 0402; AGILE_PN: 470-79965; CAD_APPROVED: Yes; FPLIST: RC0402_25,RC0402_HD,RC0402_X2,0402_CC,RC0402_X3; HEIGHT: 0.4MM; MFG_NAME01: PANASONIC; MFG_PN01: ERJ-2GE0R00X; Package: 0402; Part Number: 4RC0000B51X00; Product Name: (H)RES 0E 1/16W 0402 5% PBFREE; ROHS: Yes; Temp Range: –55 °C to +155 °C
R744 R5802 = RES: RES MF 4.7K 1/10W 5% AEC-Q200 0402; AGILE_PN: 470-82064; ASSY_OPT: DNP; CAD_APPROVED: Yes; FPLIST: RC0402_25,RC0402_HD,0402_CC,RC0402_X2; HEIGHT: 0.41mm; MFG_NAME01: KOA SPEER; MFG_PN01: RK73B1ETTP472J; ROHS: Yes; Temp Range: -55C to +155C; Tolerance: 5%
R119 R120 R124 R125 R128 R142 R143 R145 R146 R151 R206 R306-R309 R320-R323 R734 R735 R739 R740 R742 R746 R751 R753 R756 R757 R5803 R5804 = RES: RES MF 4.7K 1/10W 5% AEC-Q200 0402; AGILE_PN: 470-82064; CAD_APPROVED: Yes; FPLIST: RC0402_25,RC0402_HD,0402_CC,RC0402_X2; HEIGHT: 0.41mm; MFG_NAME01: KOA SPEER; MFG_PN01: RK73B1ETTP472J; ROHS: Yes; Temp Range: -55C to +155C; Tolerance: 5%
R5805 = RES: RES MF 5K 1/16W 1% 0402; AGILE_PN: 470-82785; CAD_APPROVED: Yes; FPLIST: RC0402_25,RC0402_HD,0402_CC; HEIGHT: 0.40MM; MFG_NAME01: YAGEO AMERICA; MFG_PN01: RC0402FR-075KL; Package Size: 0402 (1005 Metric); Tolerance: 1%
TP73-TP77 TP79-TP81 TP90 TP96 TP98-TP100 TP261-TP285 = T_POINT_TH: TEST POINT PAD 20 MILS SMT, NOT PART TO ORDER; AGILE_PN: 211-81036; CAD_APPROVED: Yes; FPLIST: tpad_020_top,tpad_020_btm_nsp; HEIGHT: 0.127MM; MFG_NAME01: NO PART ORDER; MFG_PN01: NA; ROHS: Yes
U620 = IC_88E1543_LQFP_128P_EP: IC XCVR QUAD ETHERNET 10/100/1000 PHY 3.3V LQFP128; 3D_Mechanical_Footprint_File: http://fcl.am.freescale.net/ALLEGRO/step/lqfp128_0p5_20x14_epad.STEP; AGILE_PN: 312-81220; CAD_APPROVED: Yes; HEIGHT: 1.6MM; MFG_NAME01: MARVELL SEMICONDUCTOR INC; ROHS: Yes; VOLTAGE: 1.8/2.5/3.3V
Y21 = XTAL: XTAL 25MHZ 8PF -- AEC-Q200 SMT-2; 3D_Mechanical_Footprint_File: http://fcl.am.freescale.net/ALLEGRO/step/xtal2_3p3x2p6.STEP; AGILE_PN: 230-78297; ASSY_OPT: DNP; CAD_APPROVED: Yes; HEIGHT: 0.95MM; MFG_NAME01: KYOCERA; MFG_PN01: CX3225GA25000D0PTVCC; ROHS: Yes; Temp Range: -40°C to 150°C
C1259 C1260 = CAP_NP: CAP CER 1UF 25V 10% X7R 0603; AGILE_PN: 150-30185; CAD_APPROVED: Yes; FPLIST: CC0603_OV,CC0603,0603_CC; HEIGHT: 0.9mm; MFG_NAME01: WURTH ELEKTRONIK EISOS GMBH & CO. KG (ELECTRONIC & ELECTROMEHANICAL COMP); MFG_PN01: 885012206076; Package: 0805; Package Size: 0603; Package Type: tape & reel; Part Number: 4CC105D162X00; Product Name: (H)MLCC 1uF/16V +-10% 0805 X5R PBFREE; ROHS: Yes; Rated Voltage: 25V; Temp Range: -55C to +125C; Tolerance: 10%
C5294-C5301 = CAP_NP: CAP CER 0.1uF 16V 10% X7R AEC-Q200 0402; AGILE_PN: 150-79025; CAD_APPROVED: Yes; FPLIST: CC0402_25,CC0402_HD,0402_CC,capc0402_l; HEIGHT: 0.55MM; MFG_NAME01: MURATA; MFG_PN01: GCM155R71C104KA55D; PRIORITY_PN: 021-00389; Package Size: 0402; Package Type: ø180mm Reel PAPER; ROHS: Yes; ROOM: PEX_SLOTS123_REFCLK; Rated Voltage: 16V; SIGNAL_MODEL: DEFAULT_CAPACITOR_100000pF_2_1; TOL: 10%; Temp Range: -55C to +125C; Tolerance: 10%; VOLTAGE: 35V
J11-J14 = RJ45_MAG_2X1_LED: CON 13 RJ-45 DUAL SKT SHLD RA TH G/YG LEDS 39MIL SP 1080H AU 125L; 3D_Mechanical_Footprint_File: http://fcl.am.freescale.net/ALLEGRO/step/con_rj45_2x1_mag_led.STEP; AGILE_PN: 210-76036; CAD_APPROVED: Yes; HEIGHT: 27.43 MM; MFG_NAME01: BEL FUSE; MFG_PN01: 0845-2R1T-E4; Package Size: 33.91x17.25x27.43mm; ROHS: Yes
R641-R652 R654-R656 = RES: RES MF 330 OHM 1/16W 5% 0402; AGILE_PN: 470-75613; CAD_APPROVED: Yes; FPLIST: RC0402_25,RC0402_HD,0402_CC; HEIGHT: 0.41mm; MFG_NAME01: BOURNS; MFG_PN01: CR0402-JW-331GLF; Package: 0603; Part Number: 4RC3301C11X00; Product Name: (H)RES 330E 1/10W 0603 1% PBFREE; ROHS: Yes; Tolerance: 5%
C5337-C5339 = CAP_POL: CAP ALEL 330uF 25V 20% -- RADIAL; AGILE_PN: 150-78978; CAD_APPROVED: Yes; ESR: 0.014 OHMS; HEIGHT: 13 MM; MFG_NAME01: PANASONIC; MFG_PN01: 25SEPF330M; ROHS: Yes; ROOM: VDD_GVDD_PS; Rated Voltage: 25V; Temp Range: -55C to +150C; Temp_Range: –55 °C to +105 °C; Tolerance: 20%; VOLTAGE: 25V
U55 = CONN_PCIEXP_64P_CUST_B: CON 2X32 PCI EXPRESS SMT 1MM SP 320H AU; 3D_Mechanical_Footprint_File: http://fcl.am.freescale.net/ALLEGRO/step/con64_1mm_sm_pcie_lp.step; AGILE_PN: 211-80314; CAD_APPROVED: Yes; HEIGHT: 8.13MM; MFG_NAME01: SAMTEC; ROHS: Yes; Temp Range: -55&#8451; to 125&#8451;; Temp_Range: -55&#8451; to 125&#8451;
C25 C26 C40 C41 C43 C58 C60 C65 C66 = CAP_NP: CAP CER 0.1uF 16V 10% X7R AEC-Q200 0402; AGILE_PN: 150-79025; CAD_APPROVED: Yes; FPLIST: CC0402_25,CC0402_HD,0402_CC,capc0402_l; HEIGHT: 0.55MM; MFG_NAME01: MURATA; MFG_PN01: GCM155R71C104KA55D; Package Size: 0402; Package Type: ø180mm Reel PAPER; ROHS: Yes; Rated Voltage: 16V; Temp Range: -55C to +125C; Tolerance: 10%
J3 = CONN_PCI_EXPRESS_X8: CON 98 CRD EDGE PCI EXPRESS TH OPEN-ENDED 1MM SP 443H AU 122L; 3D_Mechanical_Footprint_File: http://fcl.am.freescale.net/ALLEGRO/step/con_pcie_98_1mm_th_122l.STEP; AGILE_PN: 210-82925; CAD_APPROVED: Yes; HEIGHT: 11.25 MM; MFG_NAME01: Amphenol ICC (FCI); MFG_PN01: 10137945-10112TLF; Package Type: Through Hole; ROHS: Yes
U22 = T4240: IC MPU 64BIT T4240 1.8GHz 1.025V CRYPTO QorIQ PBGA1932; 3D_Mechanical_Footprint_File: http://fcl.am.freescale.net/ALLEGRO/step/bga1932_1mm_45x45mm.STEP; AGILE_PN: 330-77243; CAD_APPROVED: Yes; HEIGHT: 3.33 MM; MFG_NAME01: NXP SEMICONDUCTOR; Package Size: SOT1645-1; Part Number: 71F101G206X01; Product Name: (N)SOC FREESCALE:T4240NSE7TTB; ROHS: Yes; Temp Range: 0 to 105 °C
R745 = RES: RES MF 10.0 OHM 1/16W 1% 0402; 3D_Mechanical_Footprint_File: http://fcl.am.freescale.net/ALLEGRO/step/rc0402_25.STEP; AGILE_PN: 470-76090; CAD_APPROVED: Yes; FPLIST: RC0402_25,RC0402_HD,0402_CC,rc0402_ghwe; HEIGHT: 0.4MM; MFG_NAME01: BOURNS; MFG_PN01: CR0402-FX-10R0GLF; Package: 0402; Part Number: 4RC1000B11X00; Product Name: (H)RES 10E 1/16W 0402 1% PBFREE; ROHS: Yes; Tolerance: 1%
R5875 = RES: RES MF 10.0K 1/16W 1% AEC-Q200 0402; AGILE_PN: 470-75416; CAD_APPROVED: Yes; FPLIST: RC0402_25,RC0402_HD,0402_CC; HEIGHT: 0.4MM; MFG_NAME01: KOA SPEER; MFG_PN01: RK73H1ETTP1002F; PRIORITY_PN: 006-00552; ROHS: Yes; ROOM: 1V5_SB; Temp Range: –55 °C to +155 °C; Tolerance: 1%
C402 C406 C422 C425 = CAP_NP: CAP CER 0.01UF 50V 10% X7R 0402; AGILE_PN: 150-30114; CAD_APPROVED: Yes; FPLIST: CC0402_25,CC0402_HD,0402_CC,capc0402_l; HEIGHT: 0.55 MM; MFG_NAME01: MURATA; MFG_PN01: GRM155R71H103KA88D; Package: 0402; Part Number: 4CC103B501X00; Product Name: (H)MLCC 0.01uF/50V +-10% 0402 X7R; ROHS: Yes; Rated Voltage: 50V; Temp Range: -55C to +125C; Tolerance: 10%
J10 = CON_SATA_PLUG7: HDR 1X7 SMT 50 MIL CTR 331H AU; 3D_Mechanical_Footprint_File: http://fcl.am.freescale.net/ALLEGRO/step/CON_7_SATA_V_SM.STEP; AGILE_PN: 211-75318; CAD_APPROVED: Yes; HEIGHT: 8.4MM; MFG_NAME01: MOLEX; MFG_PN01: 67800-5025; ROHS: Yes; SILK: SATA
R693 R695 = RES: RES MF 698 OHM 1/16W 1% ACE-Q200 0402; AGILE_PN: 470-78342; CAD_APPROVED: Yes; FPLIST: RC0402_25,RC0402_HD,0402_CC; HEIGHT: 0.4MM; MFG_NAME01: KOA SPEER; MFG_PN01: RK73H1ETTP6980F; Package: 0402; Part Number: 4RC6981B11X00; Product Name: (H)RES 698E 1/16W 0402 1% PBFREE; ROHS: Yes; Tolerance: 1%
R694 R697 R5884-R5889 = RES: RES MF 200 Ohm 1/16W 1% AEC-Q200 0402; AGILE_PN: 470-80516; CAD_APPROVED: Yes; FPLIST: RC0402_25,RC0402_HD,0402_CC; HEIGHT: 0.4 MM; MFG_NAME01: KOA SPEER; MFG_PN01: RK73H1ETTP2000F; Package: 0402; Part Number: 4RC2001B11X00; Product Name: (H)RES 200E 1/16W 0402 1% PBFREE; ROHS: Yes; Tolerance: 1%
R700 R701 = RES: RES MF 49.9 OHM 1/10W 1% AEC-Q200 0402; AGILE_PN: 470-82539; CAD_APPROVED: YES; FPLIST: RC0402_25,RC0402_HD,0402_CC,RC0402_X2; HEIGHT: 0.4 MM; MFG_NAME01: PANASONIC; MFG_PN01: ERJ-2RKF49R9X; Package: 0402; Package Size: 0402 (1005 Metric); Part Number: 4RC4990B11X00; Product Name: (H)RES 49.9E 1/16W 0402 1% PBFREE; ROHS: YES; Temp Range: -55°C to 155°C; Tolerance: 1%

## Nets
2V5: R734.1 R735.1 R740.1 R744.1 R757.1 ; also on sheet 15 20 24 38
3V3_SB: C65.1 C412.1 J3.B10(3.3VAUX) R151.2 R206.2 U55.B10(3.3VAUX) ; also on sheet 7 9 10 51 54
GND: C25.2 C26.2 C40.2 C41.2 C43.2 C58.2 C60.2 C65.2 C66.2 C145.2 C171.2 C412.2 C434.2 C900.2 C924.2 C932.2 C936.2 C940.2 C944.2 C947.2 C950.2 C961.2 C965.2 C991.2 C992.2 C993.2 C1259.2 C1260.2 C5178.2 C5179.2 C5180.2 C5181.2 C5182.2 C5183.2 C5185.2 C5186.2 C5187.2 C5188.2 C5189.2 C5190.2 C5191.2 C5192.2 C5193.2 C5194.2 C5195.2 C5196.2 C5198.2 C5199.2 C5200.2 C5201.2 C5253.2 C5254.1 C5255.1 C5256.2 C5257.2 C5258.2 C5294.2 C5295.2 C5296.2 C5297.2 C5298.2 C5299.2 C5300.2 C5301.2 C5337.2 C5338.2 C5339.2 J3.A1(~{PRSNT1}) J3.A4(GND20) J3.A12(GND21) J3.A15(GND22) J3.A18(GND23) J3.A20(GND24) J3.A23(GND25) J3.A24(GND26) J3.A27(GND27) J3.A28(GND28) J3.A31(GND29) J3.A34(GND30) J3.A37(GND31) J3.A38(GND32) J3.A41(GND33) J3.A42(GND34) J3.A45(GND35) J3.A46(GND36) J3.A49(GND37) J3.B4(GND1) J3.B7(GND2) J3.B13(GND3) J3.B16(GND4) J3.B18(GND5) J3.B21(GND6) J3.B22(GND7) J3.B25(GND8) J3.B26(GND9) J3.B29(GND10) J3.B32(GND11) J3.B35(GND12) J3.B36(GND13) J3.B39(GND14) J3.B40(GND15) J3.B43(GND16) J3.B44(GND17) J3.B47(GND18) J3.B49(GND19) J10.1(GND) J10.4(GND) J10.7(GND) J10.M1 J10.M2 J11.1(GND2) J11.20(GND1) J12.1(GND2) J12.20(GND1) J13.1(GND2) J13.20(GND1) J14.1(GND2) J14.20(GND1) R119.2 R124.2 R142.1 R146.1 R306.2 R307.1 R308.1 R309.2 R320.2 R321.1 R322.1 R323.2 R700.2 R701.2 R739.2 R742.2 R746.2 R751.2 R753.2 R756.2 R5792.1 R5804.2 R5805.2 R5875.2 R5884.1 R5885.1 R5886.1 R5887.1 R5888.1 R5889.1 U55.A1(PRSNT#1) U55.A4(GND1) U55.A12(GND2) U55.A15(GND3) U55.A18(GND4) U55.A20(GND5) U55.A23(GND6) U55.A24(GND7) U55.A27(GND8) U55.A28(GND9) U55.A31(GND10) U55.B4(GND11) U55.B7(GND12) U55.B13(GND13) U55.B16(GND14) U55.B18(GND15) U55.B21(GND16) U55.B22(GND17) U55.B25(GND18) U55.B26(GND19) U55.B29(GND20) U55.B32(GND21) U620.67(VSS) U620.129(EPAD) ; also on sheet 6 7 8 9 10 11 12 13 14 15 16 18 19 20 21 22 24 25 27 28 29 30 31 32 33 34 35 36 37 38 39 40 41 42 49 50 51 52 53 54
VCC_3.3: C58.1 C60.1 C66.1 C434.1 C900.1 C965.1 C5338.1 FB96.1 FB98.1 J3.A9(+3.3V_1) J3.A10(+3.3V_2) J3.B8(+3.3V) J11.28(LED1_A) J11.32(LED3_A) J12.28(LED1_A) J12.32(LED3_A) J13.28(LED1_A) J13.32(LED3_A) J14.28(LED1_A) J14.32(LED3_A) R120.2 R125.2 R128.2 R143.2 R145.2 U55.A9(+3.3V1) U55.A10(+3.3V2) U55.B8(+3.3V3) ; also on sheet 6 12 13 16 18 24 25 31 32 33 36 39 40 41 42 49 50 51 53
VCC_12: C25.1 C26.1 C40.1 C41.1 C43.1 C145.1 C171.1 C991.1 C992.1 C993.1 C5337.1 C5339.1 J3.A2(+12V_4) J3.A3(+12V_5) J3.B1(+12V_1) J3.B2(+12V_2) J3.B3(+12V_3) U55.A2(+12V1) U55.A3(+12V2) U55.B1(+12V3) U55.B2(+12V4) U55.B3(+12V5) ; also on sheet 6 11 14 15 53
VDD_S3VDD: R694.2 ; also on sheet 19
VDD_S4VDD: R697.2 ; also on sheet 19
VDD_X3VDD: R693.2 ; also on sheet 19
VDD_X4VDD: R695.2 ; also on sheet 19
1G_P0_LED_ACT_N: R642.1 ; also on sheet 42
1G_P0_LINK10_100_N: J11.34(LED4_GA) ; also on sheet 42
1G_P0_LINK1000_N: R644.1 ; also on sheet 42
1G_P0_TXVA_N: J11.13(TRD1-) ; also on sheet 42
1G_P0_TXVA_P: J11.6(TRD1+) ; also on sheet 42
1G_P0_TXVB_N: J11.5(TRD2-) ; also on sheet 42
1G_P0_TXVB_P: J11.11(TRD2+) ; also on sheet 42
1G_P0_TXVC_N: J11.10(TRD3-) ; also on sheet 42
1G_P0_TXVC_P: J11.3(TRD3+) ; also on sheet 42
1G_P0_TXVD_N: J11.2(TRD4-) ; also on sheet 42
1G_P0_TXVD_P: J11.8(TRD4+) ; also on sheet 42
1G_P1_LED_ACT_N: R641.1 ; also on sheet 42
1G_P1_LINK10_100_N: R643.1 ; also on sheet 42
1G_P1_LINK1000_N: J11.30(LED2_GA) ; also on sheet 42
1G_P1_TXVA_N: J11.21(TRD1-) ; also on sheet 42
1G_P1_TXVA_P: J11.15(TRD1+) ; also on sheet 42
1G_P1_TXVB_N: J11.16(TRD2-) ; also on sheet 42
1G_P1_TXVB_P: J11.23(TRD2+) ; also on sheet 42
1G_P1_TXVC_N: J11.24(TRD3-) ; also on sheet 42
1G_P1_TXVC_P: J11.18(TRD3+) ; also on sheet 42
1G_P1_TXVD_N: J11.19(TRD4-) ; also on sheet 42
1G_P1_TXVD_P: J11.26(TRD4+) ; also on sheet 42
1G_P2_LED_ACT_N: R646.1 ; also on sheet 42
1G_P2_LINK10_100_N: R648.1 ; also on sheet 42
1G_P2_LINK1000_N: J12.34(LED4_GA) ; also on sheet 42
1G_P2_TXVA_N: J12.13(TRD1-) ; also on sheet 42
1G_P2_TXVA_P: J12.6(TRD1+) ; also on sheet 42
1G_P2_TXVB_N: J12.5(TRD2-) ; also on sheet 42
1G_P2_TXVB_P: J12.11(TRD2+) ; also on sheet 42
1G_P2_TXVC_N: J12.10(TRD3-) ; also on sheet 42
1G_P2_TXVC_P: J12.3(TRD3+) ; also on sheet 42
1G_P2_TXVD_N: J12.2(TRD4-) ; also on sheet 42
1G_P2_TXVD_P: J12.8(TRD4+) ; also on sheet 42
1G_P3_LED_ACT_N: R645.1 ; also on sheet 42
1G_P3_LINK10_100_N: R647.1 ; also on sheet 42
1G_P3_LINK1000_N: J12.30(LED2_GA) ; also on sheet 42
1G_P3_TXVA_N: J12.21(TRD1-) ; also on sheet 42
1G_P3_TXVA_P: J12.15(TRD1+) ; also on sheet 42
1G_P3_TXVB_N: J12.16(TRD2-) ; also on sheet 42
1G_P3_TXVB_P: J12.23(TRD2+) ; also on sheet 42
1G_P3_TXVC_N: J12.24(TRD3-) ; also on sheet 42
1G_P3_TXVC_P: J12.18(TRD3+) ; also on sheet 42
1G_P3_TXVD_N: J12.19(TRD4-) ; also on sheet 42
1G_P3_TXVD_P: J12.26(TRD4+) ; also on sheet 42
1G_P4_LED_ACT_N: R650.1 TP283.1(TP) U620.100(P0_LED[0])
1G_P4_LINK10_100_N: R652.1 R5797.1 R5800.1 TP282.1(TP) U620.101(P0_LED[1])
1G_P4_LINK1000_N: J13.34(LED4_GA) TP281.1(TP) U620.102(P0_LED[2])
1G_P4_TXVA_N: J13.13(TRD1-) U620.127(P0_MDIN[0])
1G_P4_TXVA_P: J13.6(TRD1+) U620.126(P0_MDIP[0])
1G_P4_TXVB_N: J13.5(TRD2-) U620.3(P0_MDIN[1])
1G_P4_TXVB_P: J13.11(TRD2+) U620.2(P0_MDIP[1])
1G_P4_TXVC_N: J13.10(TRD3-) U620.5(P0_MDIN[2])
1G_P4_TXVC_P: J13.3(TRD3+) U620.4(P0_MDIP[2])
1G_P4_TXVD_N: J13.2(TRD4-) U620.8(P0_MDIN[3])
1G_P4_TXVD_P: J13.8(TRD4+) U620.7(P0_MDIP[3])
1G_P5_LED_ACT_N: R649.1 TP279.1(TP) U620.105(P1_LED[0])
1G_P5_LINK10_100_N: R651.1 TP278.1(TP) U620.106(P1_LED[1])
1G_P5_LINK1000_N: J13.30(LED2_GA) TP277.1(TP) U620.107(P1_LED[2])
1G_P5_TXVA_N: J13.21(TRD1-) U620.18(P1_MDIN[0])
1G_P5_TXVA_P: J13.15(TRD1+) U620.19(P1_MDIP[0])
1G_P5_TXVB_N: J13.16(TRD2-) U620.15(P1_MDIN[1])
1G_P5_TXVB_P: J13.23(TRD2+) U620.16(P1_MDIP[1])
1G_P5_TXVC_N: J13.24(TRD3-) U620.12(P1_MDIN[2])
1G_P5_TXVC_P: J13.18(TRD3+) U620.13(P1_MDIP[2])
1G_P5_TXVD_N: J13.19(TRD4-) U620.9(P1_MDIN[3])
1G_P5_TXVD_P: J13.26(TRD4+) U620.10(P1_MDIP[3])
1G_P6_LED_ACT_N: R654.1 TP275.1(TP) U620.111(P2_LED[0])
1G_P6_LINK10_100_N: R656.1 TP274.1(TP) U620.112(P2_LED[1])
1G_P6_LINK1000_N: J14.34(LED4_GA) TP273.1(TP) U620.115(P2_LED[2])
1G_P6_TXVA_N: J14.13(TRD1-) U620.21(P2_MDIN[0])
1G_P6_TXVA_P: J14.6(TRD1+) U620.20(P2_MDIP[0])
1G_P6_TXVB_N: J14.5(TRD2-) U620.24(P2_MDIN[1])
1G_P6_TXVB_P: J14.11(TRD2+) U620.23(P2_MDIP[1])
1G_P6_TXVC_N: J14.10(TRD3-) U620.27(P2_MDIN[2])
1G_P6_TXVC_P: J14.3(TRD3+) U620.26(P2_MDIP[2])
1G_P6_TXVD_N: J14.2(TRD4-) U620.30(P2_MDIN[3])
1G_P6_TXVD_P: J14.8(TRD4+) U620.29(P2_MDIP[3])
1G_P7_LED_ACT_N: J14.27(LED1_C) TP271.1(TP) U620.118(P3_LED[0])
1G_P7_LINK10_100_N: R655.1 TP270.1(TP) U620.119(P3_LED[1])
1G_P7_LINK1000_N: J14.30(LED2_GA) TP269.1(TP) U620.120(P3_LED[2])
1G_P7_TXVA_N: J14.21(TRD1-) U620.40(P3_MDIN[0])
1G_P7_TXVA_P: J14.15(TRD1+) U620.41(P3_MDIP[0])
1G_P7_TXVB_N: J14.16(TRD2-) U620.36(P3_MDIN[1])
1G_P7_TXVB_P: J14.23(TRD2+) U620.37(P3_MDIP[1])
1G_P7_TXVC_N: J14.24(TRD3-) U620.34(P3_MDIN[2])
1G_P7_TXVC_P: J14.18(TRD3+) U620.35(P3_MDIP[2])
1G_P7_TXVD_N: J14.19(TRD4-) U620.31(P3_MDIN[3])
1G_P7_TXVD_P: J14.26(TRD4+) U620.32(P3_MDIP[3])
CGND: C1259.1 C1260.1 J11.S1(CHASSIS_GND1) J11.S2(CHASSIS_GND2) J11.S3(CHASSIS_GND3) J11.S4(CHASSIS_GND4) J12.S1(CHASSIS_GND1) J12.S2(CHASSIS_GND2) J12.S3(CHASSIS_GND3) J12.S4(CHASSIS_GND4) J13.S1(CHASSIS_GND1) J13.S2(CHASSIS_GND2) J13.S3(CHASSIS_GND3) J13.S4(CHASSIS_GND4) J14.S1(CHASSIS_GND1) J14.S2(CHASSIS_GND2) J14.S3(CHASSIS_GND3) J14.S4(CHASSIS_GND4) ; also on sheet 36 40 49 52
CLK_ENET2: U620.66(REF_CLKP) ; also on sheet 24
EC1_GTX_CLK125: U22.D12(EC1_GTX_CLK125) ; also on sheet 24
EC1_RX_CLK: R756.1 U22.B12(EC1_RX_CLK)
EC1_RX_DV: R320.1 U22.A13(EC1_RX_DV)
EC1_RXD0: R751.1 U22.C12(EC1_RXD0)
EC1_RXD1: R746.1 U22.E12(EC1_RXD1)
EC1_RXD2: R306.1 U22.A12(EC1_RXD2)
EC1_RXD3: R739.1 U22.G12(EC1_RXD3)
EC1_TX_CTL_S: R753.1 U22.C13(EC1_TX_EN)
EC2_GTX_CLK125: U22.E10(EC2_GTX_CLK125) ; also on sheet 24
EC2_RX_CLK: R323.1 U22.B10(EC2_RX_CLK)
EC2_RX_DV: R309.1 U22.C10(EC2_RX_DV)
EC2_RXD0: R308.2 U22.A10(EC2_RXD0)
EC2_RXD1: R321.2 U22.A11(EC2_RXD1)
EC2_RXD2: R307.2 U22.C11(EC2_RXD2)
EC2_RXD3: R322.2 U22.D10(EC2_RXD3)
EC2_TX_CTL_S: R742.1 U22.G10(EC2_TX_EN)
EMI2_MDC: TP284.1(TP) U22.D13(EMI2_MDC)
EMI2_MDIO: R5875.1 TP285.1(TP) U22.E13(EMI2_MDIO)
I2C1_CH6_SCL: U55.B5(SMCLK) ; also on sheet 50
I2C1_CH6_SDA: U55.B6(SMDAT) ; also on sheet 50
I2C2_SCL: J3.B5(SMCLK) ; also on sheet 50
I2C2_SDA: J3.B6(SMDAT) ; also on sheet 50
INT_PHY1_B: U620.99(~{INT}) ; also on sheet 8
PCIE_4X_TCK: R124.1 U55.A5(TCK)
PCIE_4X_TDI: R125.1 U55.A6(TDI)
PCIE_4X_TMS: R143.1 U55.A8(TMS)
PCIE_4X_TRST_B: R146.2 U55.B9(+TRST#)
PCIE_REFCLK_N: J3.A14(REFCLK-) ; also on sheet 25
PCIE_REFCLK_P: J3.A13(REFCLK+) ; also on sheet 25
PCIE_X4_CLK_N: U55.A14(REFCLK-) ; also on sheet 25
PCIE_X4_CLK_P: U55.A13(REFCLK+) ; also on sheet 25
PCIEX4_WAKE_B: R206.1 U55.B11(WAKE#)
PCIEX8_WAKE_B: J3.B11(~{WAKE}) R151.1
PHY1_AVDD18: C5185.1 C5186.1 C5187.1 C5188.1 C5189.1 C5190.1 C5191.1 C5192.1 C5193.1 C5194.1 C5195.1 C5196.1 C5258.1 FB97.2 U620.6(AVDD18_1) U620.11(AVDD18_2) U620.17(AVDD18_3) U620.22(AVDD18_4) U620.28(AVDD18_5) U620.33(AVDD18_6) U620.39(AVDD18_7) U620.70(AVDD18_8) U620.75(AVDD18_9) U620.78(AVDD18_10) U620.89(AVDD18_11) U620.94(AVDD18_12) U620.128(AVDD18_13)
PHY1_AVDD33: C5180.1 C5181.1 C5182.1 C5183.1 C5257.1 FB96.2 U620.1(AVDD33) U620.14(AVDD33_2) U620.25(AVDD33_3) U620.38(AVDD33_4)
PHY1_CF0: R5797.2 U620.122(CONFIG[0])
PHY1_CF1: R5798.2 U620.123(CONFIG[1])
PHY1_CF2: R5799.2 U620.124(CONFIG[2])
PHY1_CF3: R5800.2 U620.125(CONFIG[3])
PHY1_CKRN: C5253.1 U620.65(REF_CLKN)
PHY1_CLKSEL0: R5803.2 U620.51(CLK_SEL[0])
PHY1_CLKSEL1: R5802.2 R5804.1 U620.52(CLK_SEL[1])
PHY1_HTN: TP262.1(TP) U620.44(HSDACN)
PHY1_HTP: TP261.1(TP) U620.45(HSDACP)
PHY1_NTRST: TP267.1(TP) U620.62(~{TRST})
PHY1_RSET: R5805.1 U620.42(RSET)
PHY1_TCK: TP263.1(TP) U620.54(TCK)
PHY1_TDI: TP264.1(TP) U620.58(TDI)
PHY1_TDO: TP265.1(TP) U620.61(TDO)
PHY1_TMS: TP266.1(TP) U620.55(TMS)
PHY1_VDDORL: C5178.1 C5179.1 C5198.1 C5199.1 C5200.1 FB98.2 R5798.1 R5799.1 R5802.1 R5803.1 U620.56(VDDOR1) U620.64(VDDOR2) U620.83(VDDOM) U620.98(VDDOL1) U620.110(VDDOL2) U620.117(VDDOL3)
PHY_1V0: FB95.1 ; also on sheet 14 42
PHY_1V8: FB97.1 FB99.1 ; also on sheet 15 42
PHY_EMI1_MDC: R744.2 R745.2 U620.82(MDC) ; also on sheet 42
PHY_EMI1_MDIO: R740.2 U22.H13(EMI1_MDIO) U620.81(MDIO) ; also on sheet 42
R_SD4_RX4_N: R5885.2 U22.BA30(~{SD4_RX4})
R_SD4_RX4_P: R5884.2 U22.BB30(SD4_RX4)
R_SD4_RX5_N: R5887.2 U22.BC31(~{SD4_RX5})
R_SD4_RX5_P: R5886.2 U22.BD31(SD4_RX5)
R_SD4_RX7_N: R5889.2 U22.BC33(~{SD4_RX7})
R_SD4_RX7_P: R5888.2 U22.BD33(SD4_RX7)
RST_PCIE_X4_B: U55.A11(PWRGD) ; also on sheet 8
RST_PCIE_X8_B: J3.A11(~{PERST}) R145.1 ; also on sheet 8
RST_PHY_1G_B: U620.97(~{RESET}) ; also on sheet 8 42
SD2_RX4_N: U620.92(P0_S_OUTN) ; also on sheet 37
SD2_RX4_P: U620.93(P0_S_OUTP) ; also on sheet 37
SD2_RX5_N: U620.91(P1_S_OUTN) ; also on sheet 37
SD2_RX5_P: U620.90(P1_S_OUTP) ; also on sheet 37
SD2_RX6_N: U620.73(P2_S_OUTN) ; also on sheet 37
SD2_RX6_P: U620.74(P2_S_OUTP) ; also on sheet 37
SD2_RX7_N: U620.72(P3_S_OUTN) ; also on sheet 37
SD2_RX7_P: U620.71(P3_S_OUTP) ; also on sheet 37
SD2_TX4_N: U620.95(P0_S_INN) ; also on sheet 37
SD2_TX4_P: U620.96(P0_S_INP) ; also on sheet 37
SD2_TX5_N: U620.88(P1_S_INN) ; also on sheet 37
SD2_TX5_P: U620.87(P1_S_INP) ; also on sheet 37
SD2_TX6_N: U620.76(P2_S_INN) ; also on sheet 37
SD2_TX6_P: U620.77(P2_S_INP) ; also on sheet 37
SD2_TX7_N: U620.69(P3_S_INN) ; also on sheet 37
SD2_TX7_P: U620.68(P3_S_INP) ; also on sheet 37
SD3_IMP_CAL_RX: R694.1 U22.AN19(SD3_IMP_CAL_RX)
SD3_IMP_CAL_TX: R693.1 U22.AN25(SD3_IMP_CAL_TX)
SD3_PLL1_TPA: TP76.1(TP) U22.AN21(SD3_PLL1_TPA)
SD3_PLL1_TPD: TP75.1(TP) U22.AP19(SD3_PLL1_TPD)
SD3_PLL2_TPA: TP77.1(TP) U22.AN23(SD3_PLL2_TPA)
SD3_PLL2_TPD: TP79.1(TP) U22.AP25(SD3_PLL2_TPD)
SD3_REFCLK1_N: U22.AL22(~{SD3_REF_CLK1}) ; also on sheet 25
SD3_REFCLK1_P: U22.AL21(SD3_REF_CLK1) ; also on sheet 25
SD3_REFCLK2_N: R700.1 U22.AM24(~{SD3_REF_CLK2})
SD3_REFCLK2_P: R701.1 U22.AL24(SD3_REF_CLK2)
SD3_RX0_N: J3.A17(PERN0) U22.BA18(~{SD3_RX0})
SD3_RX0_P: J3.A16(PERP0) U22.BB18(SD3_RX0)
SD3_RX1_N: J3.A22(PERN1) U22.BC19(~{SD3_RX1})
SD3_RX1_P: J3.A21(PERP1) U22.BD19(SD3_RX1)
SD3_RX2_N: J3.A26(PERN2) U22.BA20(~{SD3_RX2})
SD3_RX2_P: J3.A25(PERP2) U22.BB20(SD3_RX2)
SD3_RX3_N: J3.A30(PERN3) U22.BC21(~{SD3_RX3})
SD3_RX3_P: J3.A29(PERP3) U22.BD21(SD3_RX3)
SD3_RX4_N: J3.A36(PERN4) U22.BA22(~{SD3_RX4})
SD3_RX4_P: J3.A35(PERP4) U22.BB22(SD3_RX4)
SD3_RX5_N: J3.A40(PERN5) U22.BC23(~{SD3_RX5})
SD3_RX5_P: J3.A39(PERP5) U22.BD23(SD3_RX5)
SD3_RX6_N: J3.A44(PERN6) U22.BA24(~{SD3_RX6})
SD3_RX6_P: J3.A43(PERP6) U22.BB24(SD3_RX6)
SD3_RX7_N: J3.A48(PERN7) U22.BC25(~{SD3_RX7})
SD3_RX7_P: J3.A47(PERP7) U22.BD25(SD3_RX7)
SD3_TX0_N: C78.1 U22.AT18(~{SD3_TX0})
SD3_TX0_P: C76.1 U22.AU18(SD3_TX0)
SD3_TX1_N: C80.1 U22.AV19(~{SD3_TX1})
SD3_TX1_P: C79.1 U22.AW19(SD3_TX1)
SD3_TX2_N: C82.1 U22.AT20(~{SD3_TX2})
SD3_TX2_P: C81.1 U22.AU20(SD3_TX2)
SD3_TX3_N: C90.1 U22.AV21(~{SD3_TX3})
SD3_TX3_P: C88.1 U22.AW21(SD3_TX3)
SD3_TX4_N: C96.1 U22.AT22(~{SD3_TX4})
SD3_TX4_P: C95.1 U22.AU22(SD3_TX4)
SD3_TX5_N: C108.1 U22.AV23(~{SD3_TX5})
SD3_TX5_P: C103.1 U22.AW23(SD3_TX5)
SD3_TX6_N: C126.1 U22.AT24(~{SD3_TX6})
SD3_TX6_P: C118.1 U22.AU24(SD3_TX6)
SD3_TX7_N: C149.1 U22.AV25(~{SD3_TX7})
SD3_TX7_P: C147.1 U22.AW25(SD3_TX7)
SD3_TXC0_N: C78.2 J3.B15(PETN0)
SD3_TXC0_P: C76.2 J3.B14(PETP0)
SD3_TXC1_N: C80.2 J3.B20(PETN1)
SD3_TXC1_P: C79.2 J3.B19(PETP1)
SD3_TXC2_N: C82.2 J3.B24(PETN2)
SD3_TXC2_P: C81.2 J3.B23(PETP2)
SD3_TXC3_N: C90.2 J3.B28(PETN3)
SD3_TXC3_P: C88.2 J3.B27(PETP3)
SD3_TXC4_N: C96.2 J3.B34(PETN4)
SD3_TXC4_P: C95.2 J3.B33(PETP4)
SD3_TXC5_N: C108.2 J3.B38(PETN5)
SD3_TXC5_P: C103.2 J3.B37(PETP5)
SD3_TXC6_N: C126.2 J3.B42(PETN6)
SD3_TXC6_P: C118.2 J3.B41(PETP6)
SD3_TXC7_N: C149.2 J3.B46(PETN7)
SD3_TXC7_P: C147.2 J3.B45(PETP7)
SD4_IMP_CAL_RX: R697.1 U22.AN26(SD4_IMP_CAL_RX)
SD4_IMP_CAL_TX: R695.1 U22.AN32(SD4_IMP_CAL_TX)
SD4_PLL1_TPA: TP80.1(TP) U22.AN28(SD4_PLL1_TPA)
SD4_PLL1_TPD: TP73.1(TP) U22.AP26(SD4_PLL1_TPD)
SD4_PLL2_TPA: TP81.1(TP) U22.AN30(SD4_PLL2_TPA)
SD4_PLL2_TPD: TP74.1(TP) U22.AP32(SD4_PLL2_TPD)
SD4_REFCLK1_N: U22.AM27(~{SD4_REF_CLK1}) ; also on sheet 25
SD4_REFCLK1_P: U22.AL27(SD4_REF_CLK1) ; also on sheet 25
SD4_REFCLK2_N: U22.AL29(~{SD4_REF_CLK2}) ; also on sheet 25
SD4_REFCLK2_P: U22.AL30(SD4_REF_CLK2) ; also on sheet 25
SD4_RX0_N: U22.BA26(~{SD4_RX0}) U55.A17(HSIN(0))
SD4_RX0_P: U22.BB26(SD4_RX0) U55.A16(HSIP(0))
SD4_RX1_N: U22.BC27(~{SD4_RX1}) U55.A22(HSIN(1))
SD4_RX1_P: U22.BD27(SD4_RX1) U55.A21(HSIP(1))
SD4_RX2_N: U22.BA28(~{SD4_RX2}) U55.A26(HSIN(2))
SD4_RX2_P: U22.BB28(SD4_RX2) U55.A25(HSIP(2))
SD4_RX3_N: U22.BC29(~{SD4_RX3}) U55.A30(HSIN(3))
SD4_RX3_P: U22.BD29(SD4_RX3) U55.A29(HSIP(3))
SD4_RX6_N: C402.1 U22.BA32(~{SD4_RX6})
SD4_RX6_P: C406.1 U22.BB32(SD4_RX6)
SD4_RXC6_N: C406.2 J10.5(RXn)
SD4_RXC6_P: C402.2 J10.6(RXp)
SD4_TX0_N: C482.1 U22.AT26(~{SD4_TX0})
SD4_TX0_P: C481.1 U22.AU26(SD4_TX0)
SD4_TX1_N: C997.1 U22.AV27(~{SD4_TX1})
SD4_TX1_P: C996.1 U22.AW27(SD4_TX1)
SD4_TX2_N: C999.1 U22.AT28(~{SD4_TX2})
SD4_TX2_P: C998.1 U22.AU28(SD4_TX2)
SD4_TX3_N: C1001.1 U22.AV29(~{SD4_TX3})
SD4_TX3_P: C1000.1 U22.AW29(SD4_TX3)
SD4_TX6_N: C422.1 U22.AT32(~{SD4_TX6})
SD4_TX6_P: C425.1 U22.AU32(SD4_TX6)
SD4_TXC0_N: C482.2 U55.B15(HSON(0))
SD4_TXC0_P: C481.2 U55.B14(HSOP(0))
SD4_TXC1_N: C997.2 U55.B20(HSON(1))
SD4_TXC1_P: C996.2 U55.B19(HSOP(1))
SD4_TXC2_N: C999.2 U55.B24(HSON(2))
SD4_TXC2_P: C998.2 U55.B23(HSOP(2))
SD4_TXC3_N: C1001.2 U55.B28(HSON(3))
SD4_TXC3_P: C1000.2 U55.B27(HSOP(3))
SD4_TXC6_N: C422.2 J10.3(TXn)
SD4_TXC6_P: C425.2 J10.2(TXp)
SLOT6_TCK: J3.A5(JTAG_TCK) R119.1
SLOT6_TDI: J3.A6(JTAG_TDI) R120.1
SLOT6_TMS: J3.A8(JTAG_TMS) R128.1
SLOT6_TRST_B: J3.B9(JTAG_~{TRST}) R142.2
TSEC_1588_ALARM1_S: TP99.1(TP) U22.K13(TSEC_1588_ALARM_OUT1)
TSEC_1588_ALARM2_S: TP98.1(TP) U22.J12(TSEC_1588_ALARM_OUT2)
TSEC_1588_CLK_IN: R757.2 U22.A14(TSEC_1588_CLK_IN)
TSEC_1588_CLKOUT_S: TP100.1(TP) U22.F14(TSEC_1588_CLK_OUT)
TSEC_1588_PULSE1_S: TP90.1(TP) U22.M14(TSEC_1588_PULSE_OUT1)
TSEC_1588_PULSE2_S: TP96.1(TP) U22.L13(TSEC_1588_PULSE_OUT2)
TSEC_1588_TRIG_IN1: R735.2 U22.N15(TSEC_1588_TRIG_IN1)
TSEC_1588_TRIG_IN2: R734.2 U22.N14(TSEC_1588_TRIG_IN2)
UTEMI1_MDC: R745.1 U22.G13(EMI1_MDC)
N20471515: J11.27(LED1_C) R641.2
N20471595: J11.29(LED2_GC) R643.2
N32062690: J11.33(LED4_GC) R644.2
N32062836: J11.31(LED3_C) R642.2
N32065877: J12.31(LED3_C) R646.2
N32065910: J12.33(LED4_GC) R648.2
N32070236: J13.31(LED3_C) R650.2
N32070242: J13.33(LED4_GC) R652.2
N32070301: J13.27(LED1_C) R649.2
N32070307: J13.29(LED2_GC) R651.2
N32070366: J14.31(LED3_C) R654.2
N32070372: J14.33(LED4_GC) R656.2
N32070429: J14.29(LED2_GC) R655.2
N32074017: J12.29(LED2_GC) R647.2
N32074023: J12.27(LED1_C) R645.2
N32114156: C5254.2 U620.49(XTAL_IN) Y21.1
N32114159: C5255.2 U620.50(XTAL_OUT) Y21.2
N32114233: C924.1 C932.1 C936.1 C940.1 C944.1 C947.1 C950.1 C961.1 C5256.1 FB95.2 U620.53(DVDD1) U620.57(DVDD2) U620.63(DVDD3) U620.79(DVDD4) U620.86(DVDD5) U620.104(DVDD6) U620.109(DVDD7) U620.113(DVDD8)
N32114429: R5792.2 U620.114(V18_L)
N32114439: C5201.1 FB99.2 U620.43(VDDC1) U620.48(VDDC2)
N32114457: TP280.1(TP) U620.103(P0_LED[3])
N32114465: TP276.1(TP) U620.108(P1_LED[3])
N32114473: TP272.1(TP) U620.116(P2_LED[3])
N32114475: TP268.1(TP) U620.121(P3_LED[3])
N33883272: C5294.1 J11.4(TRCT3) J11.7(TRCT1) J11.9(TRCT4) J11.12(TRCT2)
N33883466: C5295.1 J11.14(TRCT1) J11.17(TRCT3) J11.22(TRCT2) J11.25(TRCT4)
N33883565: C5296.1 J12.4(TRCT3) J12.7(TRCT1) J12.9(TRCT4) J12.12(TRCT2)
N33883665: C5297.1 J12.14(TRCT1) J12.17(TRCT3) J12.22(TRCT2) J12.25(TRCT4)
N33884495: C5298.1 J13.4(TRCT3) J13.7(TRCT1) J13.9(TRCT4) J13.12(TRCT2)
N33884597: C5299.1 J13.14(TRCT1) J13.17(TRCT3) J13.22(TRCT2) J13.25(TRCT4)
N33884700: C5300.1 J14.4(TRCT3) J14.7(TRCT1) J14.9(TRCT4) J14.12(TRCT2)
N33884804: C5301.1 J14.14(TRCT1) J14.17(TRCT3) J14.22(TRCT2) J14.25(TRCT4)

Not connected (* = marked no-connect by the designer): J3 A7(JTAG_TDO)* A19(RSVD3)* A32(RSVD4)* A33(RSVD5)* B12(RSVD1)* B17(~{PRSNT2}_1)* B30(RSVD2)* B31(~{PRSNT2}_2)* B48(~{PRSNT2}_3)*; U22 AT30(~{SD4_TX4})* AU30(SD4_TX4)* AV31(~{SD4_TX5})* AV33(~{SD4_TX7})* AW31(SD4_TX5)* AW33(SD4_TX7)* D11(EC2_TXD0)* F10(EC2_TXD1)* F11(EC2_TXD2)* F12(EC1_GTX_CLK)* G11(EC2_TXD3)* H10(EC2_GTX_CLK)* H12(EC1_TXD0)* K12(EC1_TXD1)* L12(EC1_TXD2)* M12(EC1_TXD3)*; U55 A7(TDO)* A19(RSVD1)* A32(RSVD2)* B12(RSVD3)* B17(PRSNT#2)* B30(RSVD4)* B31(PRSNT#3)*; U620 46(TSTPT)* 47(NC1)* 59(NC2)* 60(NC3)* 80(TSTPTF)* 84(TEST[1])* 85(TEST[0])*

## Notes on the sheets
sheet 43
- 1GE PHY #2
- SGMII to SERDES 2
- \------------------------------------------------------VDDOL-----------------------------------------------------/
- CONFIGURATION
  =============================
  PHY ADDR = 0x04 ... 0x07
  ADVERTISE= all
  DEFAULT  = powered down, auto-cross, auto-neg
  MODE     = SGMII to Copper
  =============================
  CONFIG0 ::  PHY_ORD=0  PHYAD4=0     PHYAD3=0     PHYAD2=1  => 0001   => to P0_LED[1]
  CONFIG1 ::  SEL_MS=1   ENA_PAUSE=1  CANEG1=1     CANEG0=1  => 1111   => to VDDO
  CONFIG2 ::  SQ_ANEG=1  ENA_XC=1     DIS_SLEEP=1  PDOWN=1   => 1111   => to VDDO
  CONFIG3 ::  RSVD=0     MODE2=0      MODE1=0      MODE0=1   => 0001   => to P0_LED[1]
- VDDOM
- VDDOL
- \---------------------VDDOR--------------------/
- CLK_SEL[1:0]
  ===========
  00= REFCLK(P,N) = 156.25 MHz
  01= REFCLK(P,N) = 125.00 MHz
  10= REFCLK(P,N) = 25.00 MHz
  11= XTAL 25 MHz
- GUARD RING
- V18_L
  0=VDDOL = 2.5V/3.3V
  Z=VDDOL = 1.8V
sheet 44
- 1GE PORTS 1-8
sheet 45
- T4240 MDIO + RGMII
- MDIO CLAUSE 45 (1.2V) was
  used for CS4340 10G PHY only -
  no longer supported.
- 2V5 MDIO
  Use for 10/100/1G ENet PHY
sheet 46
- BACK SIDE SERDES 3 & 4  (PCIe / SATA )
- PCIE x8
- PCIE x8
- PCIE x4
- PCIE x4
- SATA
- SATA
- SATA
- SerDes 3 configuration
  ====================================================
  RCW[SRDS_PRTCL_S3]=           1- PCIe1 x8
  PLL mapping=                  11111111
  RCW[SRDS_PLL_PD_S3]=          01
  RCW[SRDS_PLL_REF_CLK_SEL_S3]= 0: PLL1=100MHz
- SerDes 4 configuration
  ====================================================
  RCW[SRDS_PRTCL_S4]=           9/11- PCIe3 x4, Unused x2, SATA1 & Unused
  PLL mapping=                  11111122
  RCW[SRDS_PLL_PD_S4]=          00
  RCW[SRDS_PLL_REF_CLK_SEL_S4]= 00: PLL1=100MHz & PLL2=100MHz
sheet 47
- PCIE SLOT #1: x4
sheet 48
- PCIE SLOT #2: x8
- VCC_12 : 2100mA
  VCC_3.3 :3000mA
